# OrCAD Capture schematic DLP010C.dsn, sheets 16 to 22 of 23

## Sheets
16 PAGE 15 - DMD FLEX B: size Custom
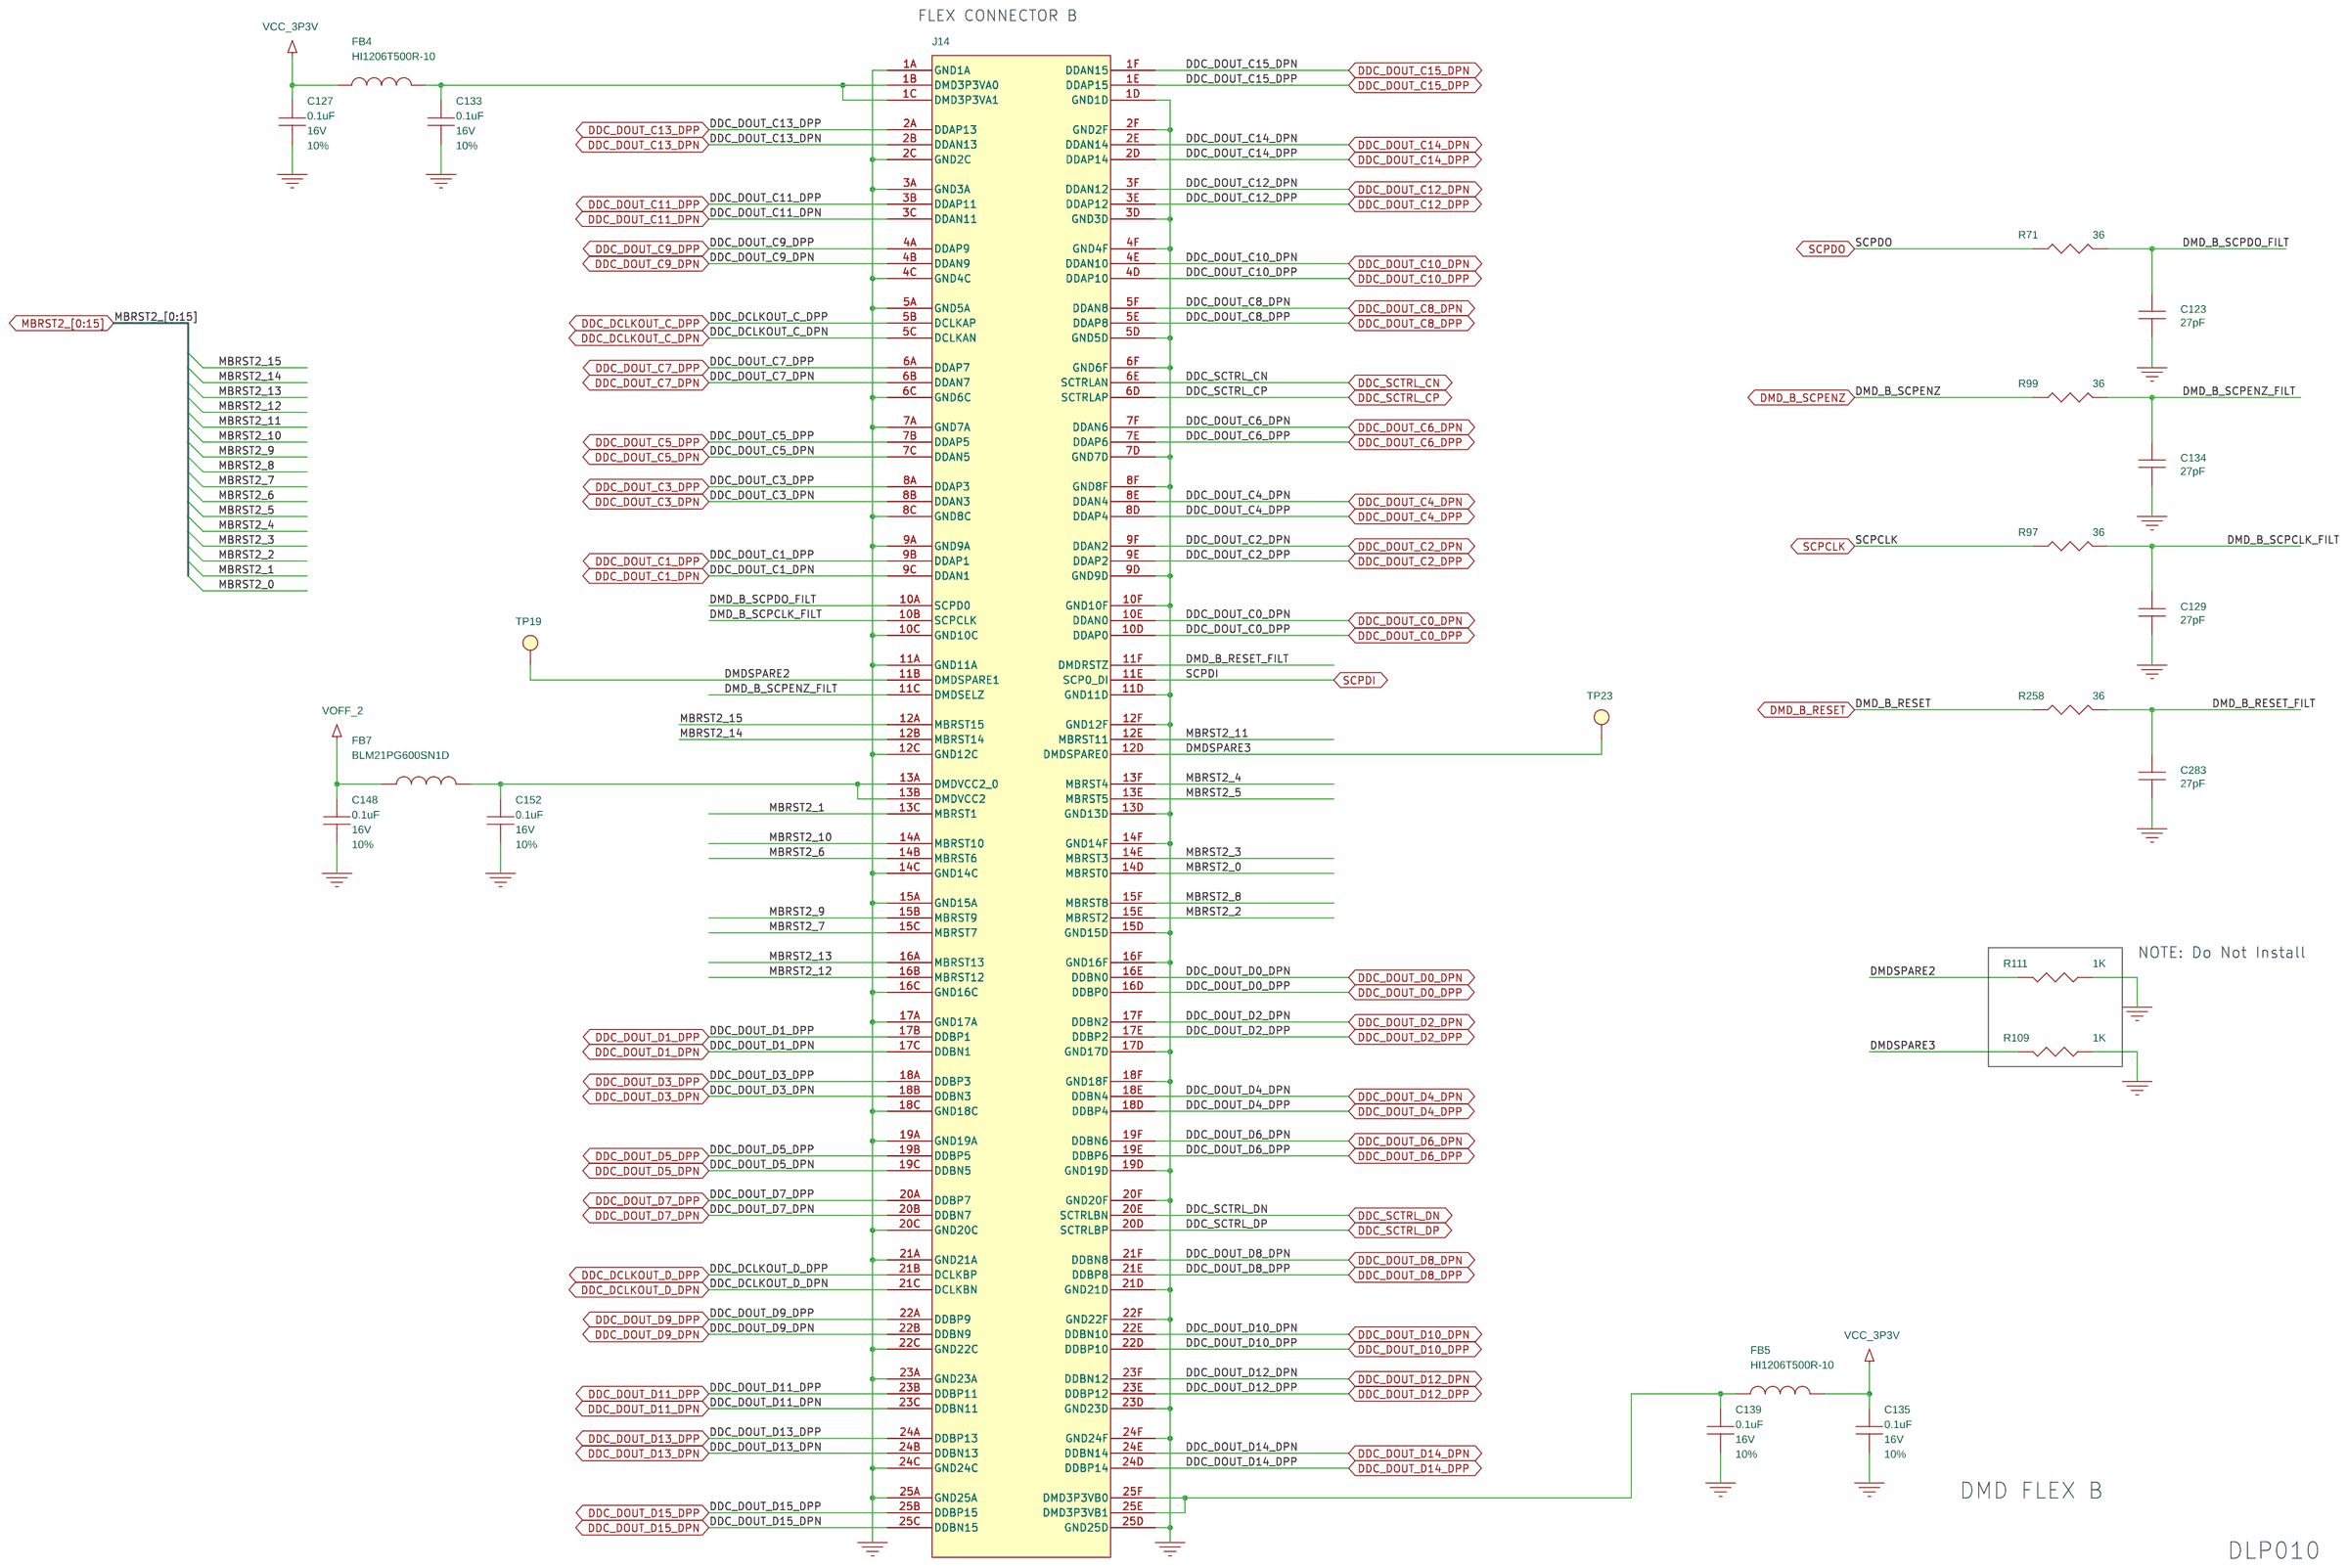
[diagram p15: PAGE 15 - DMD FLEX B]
17 PAGE 16 - EXP CONNECTOR 1: size Custom
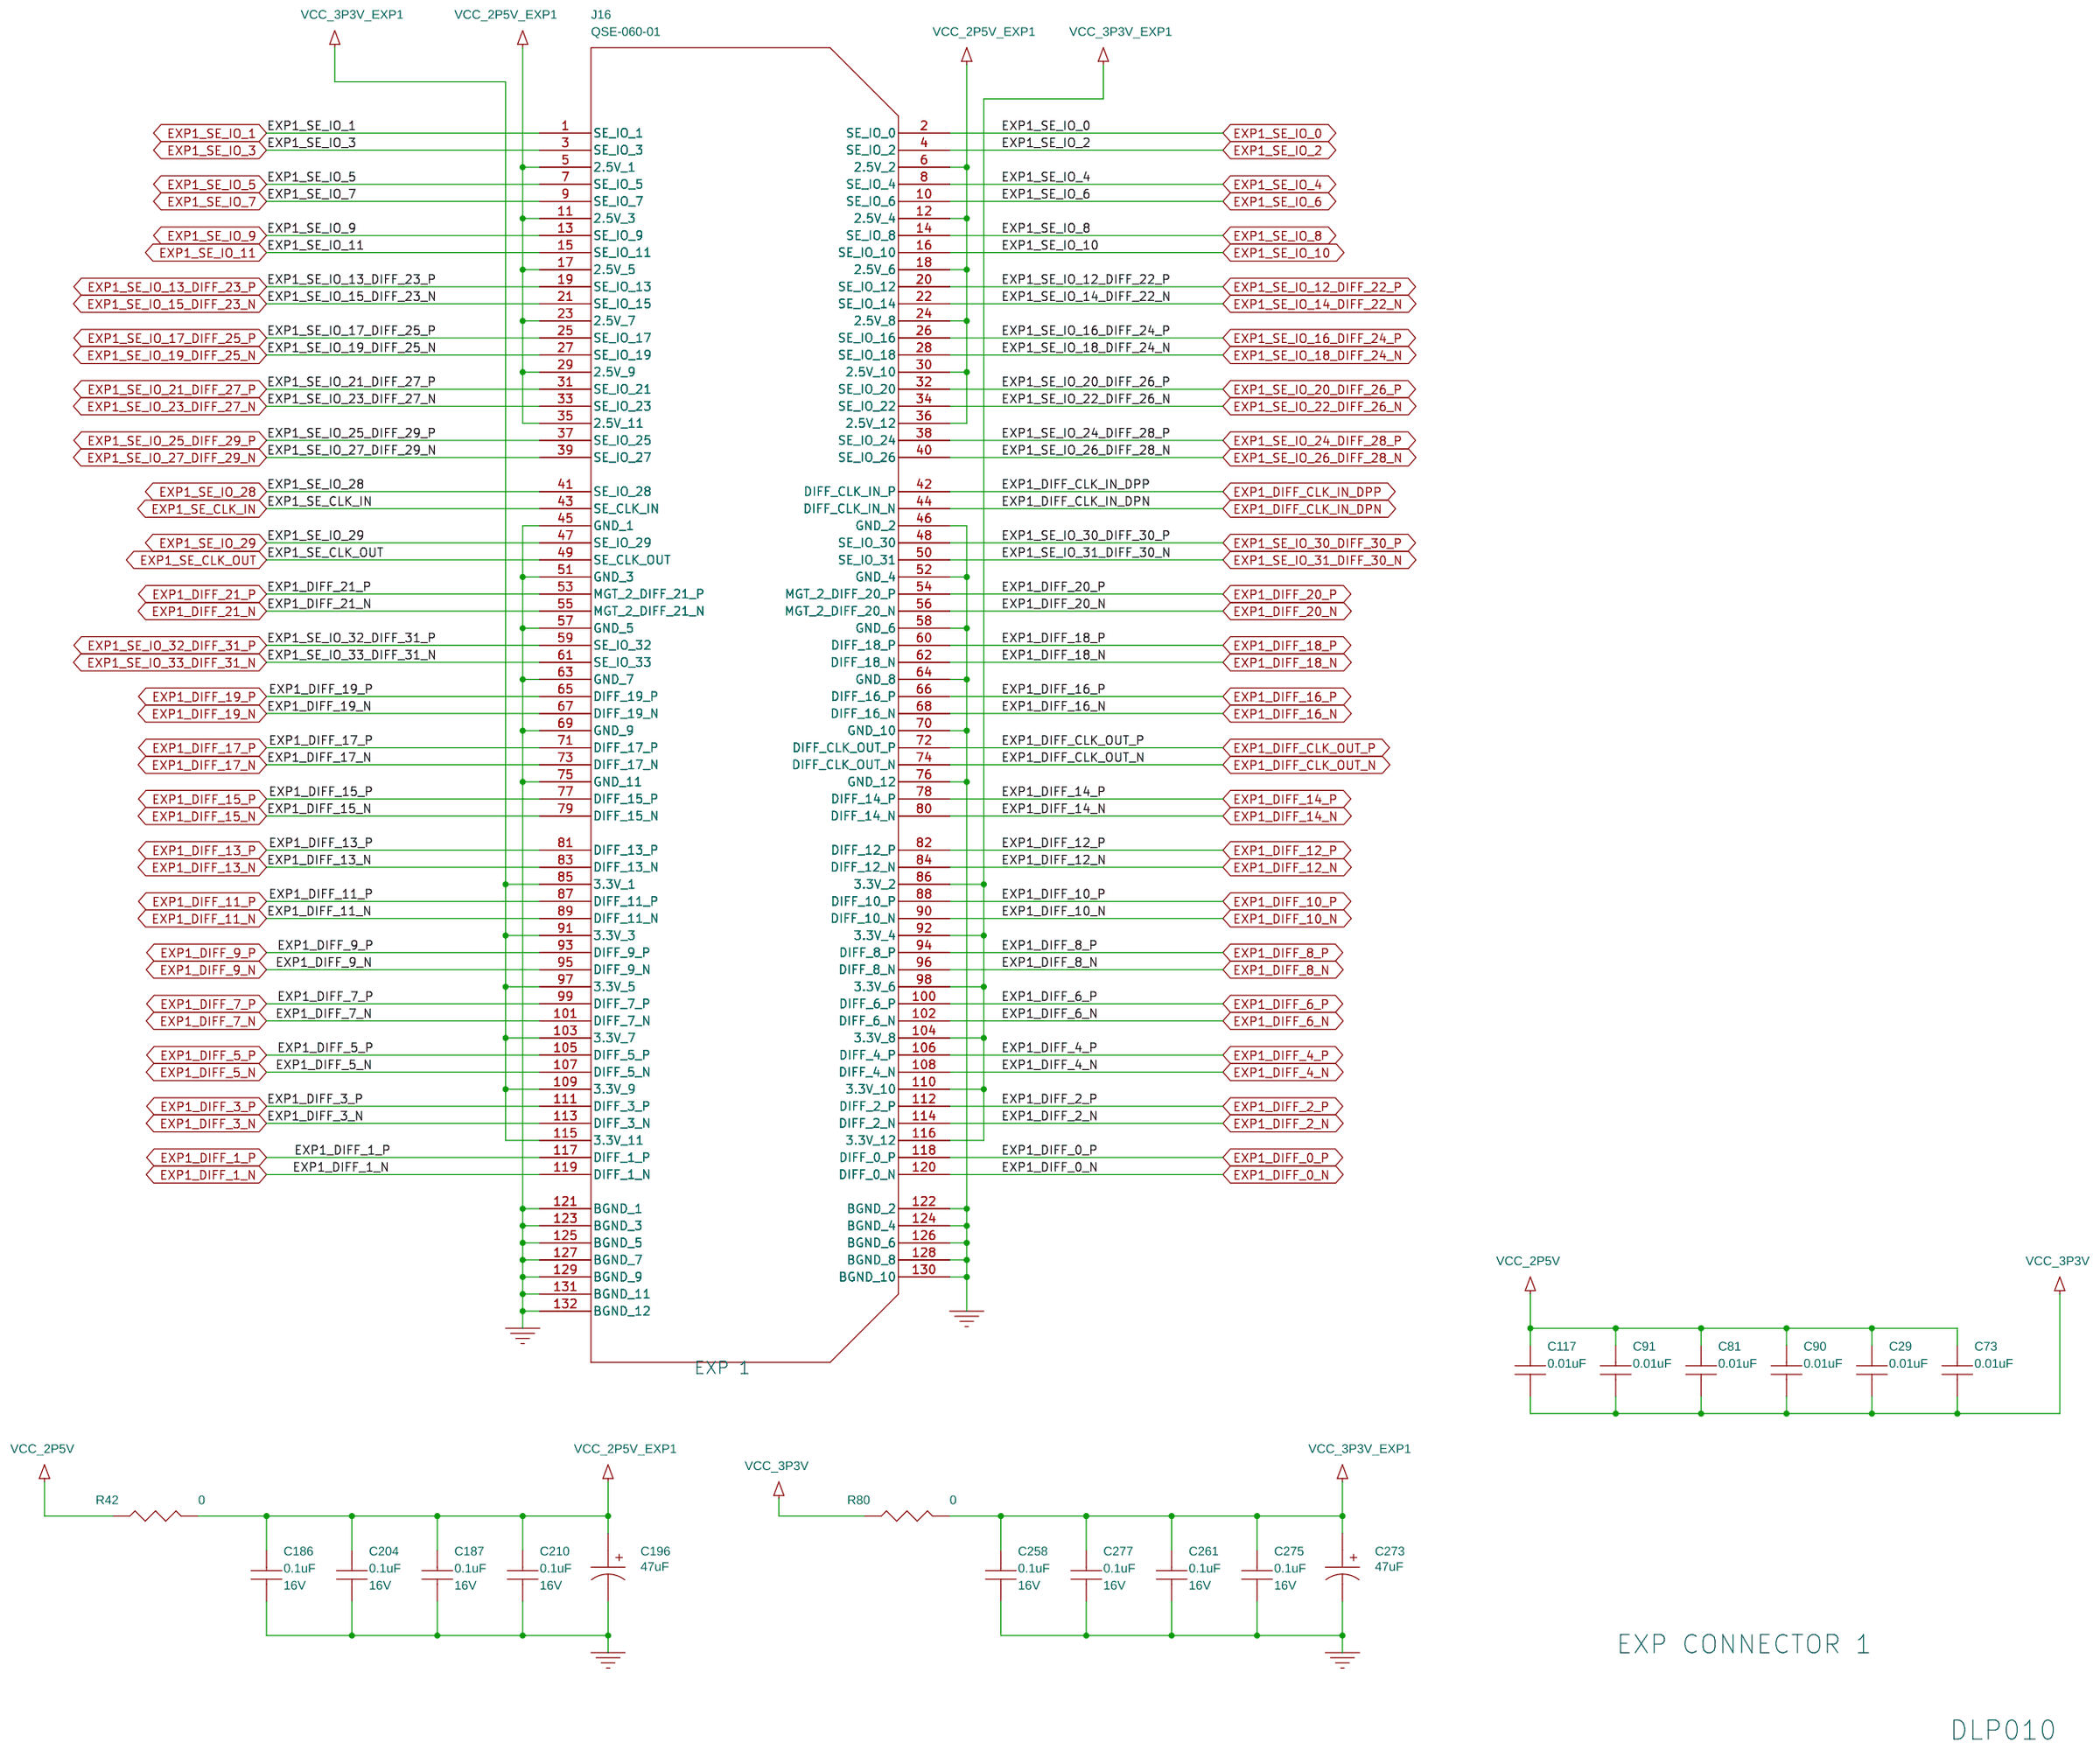
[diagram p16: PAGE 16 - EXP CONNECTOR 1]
18 PAGE 17 - EXP CONNECTOR 2: size Custom
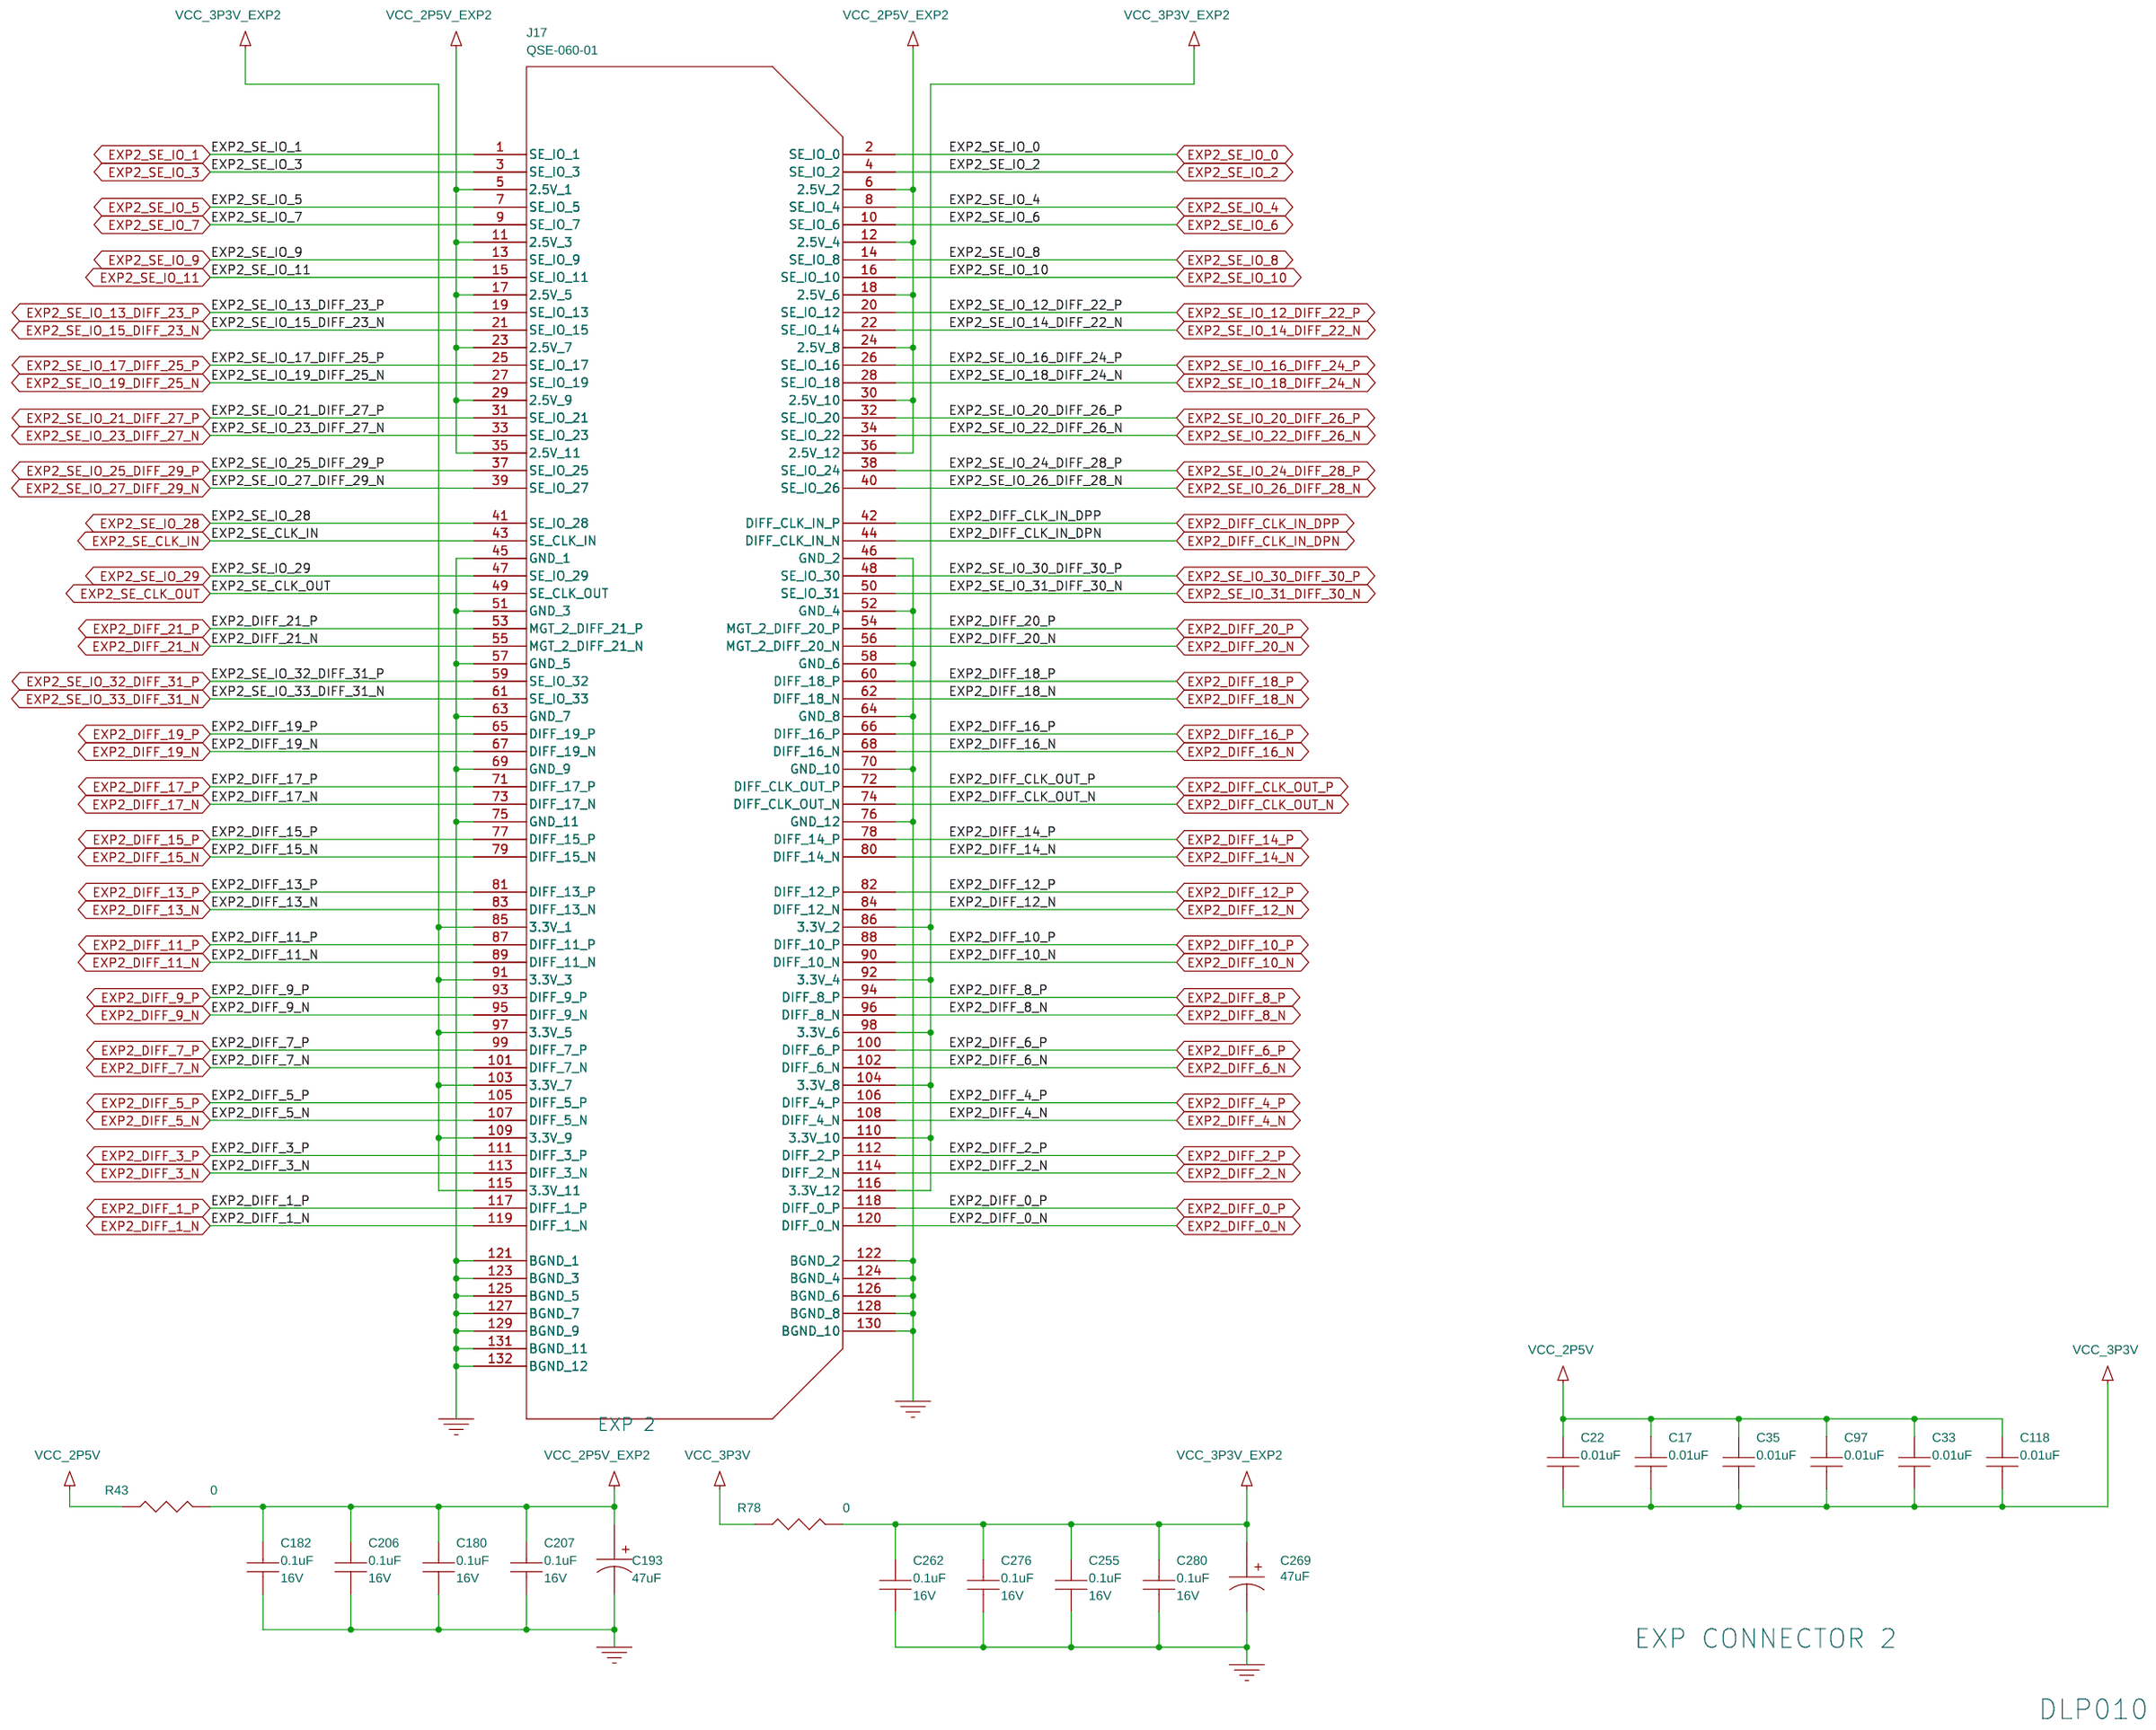
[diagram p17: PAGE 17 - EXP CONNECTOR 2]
19 PAGE 18 - POWER 1: size Custom
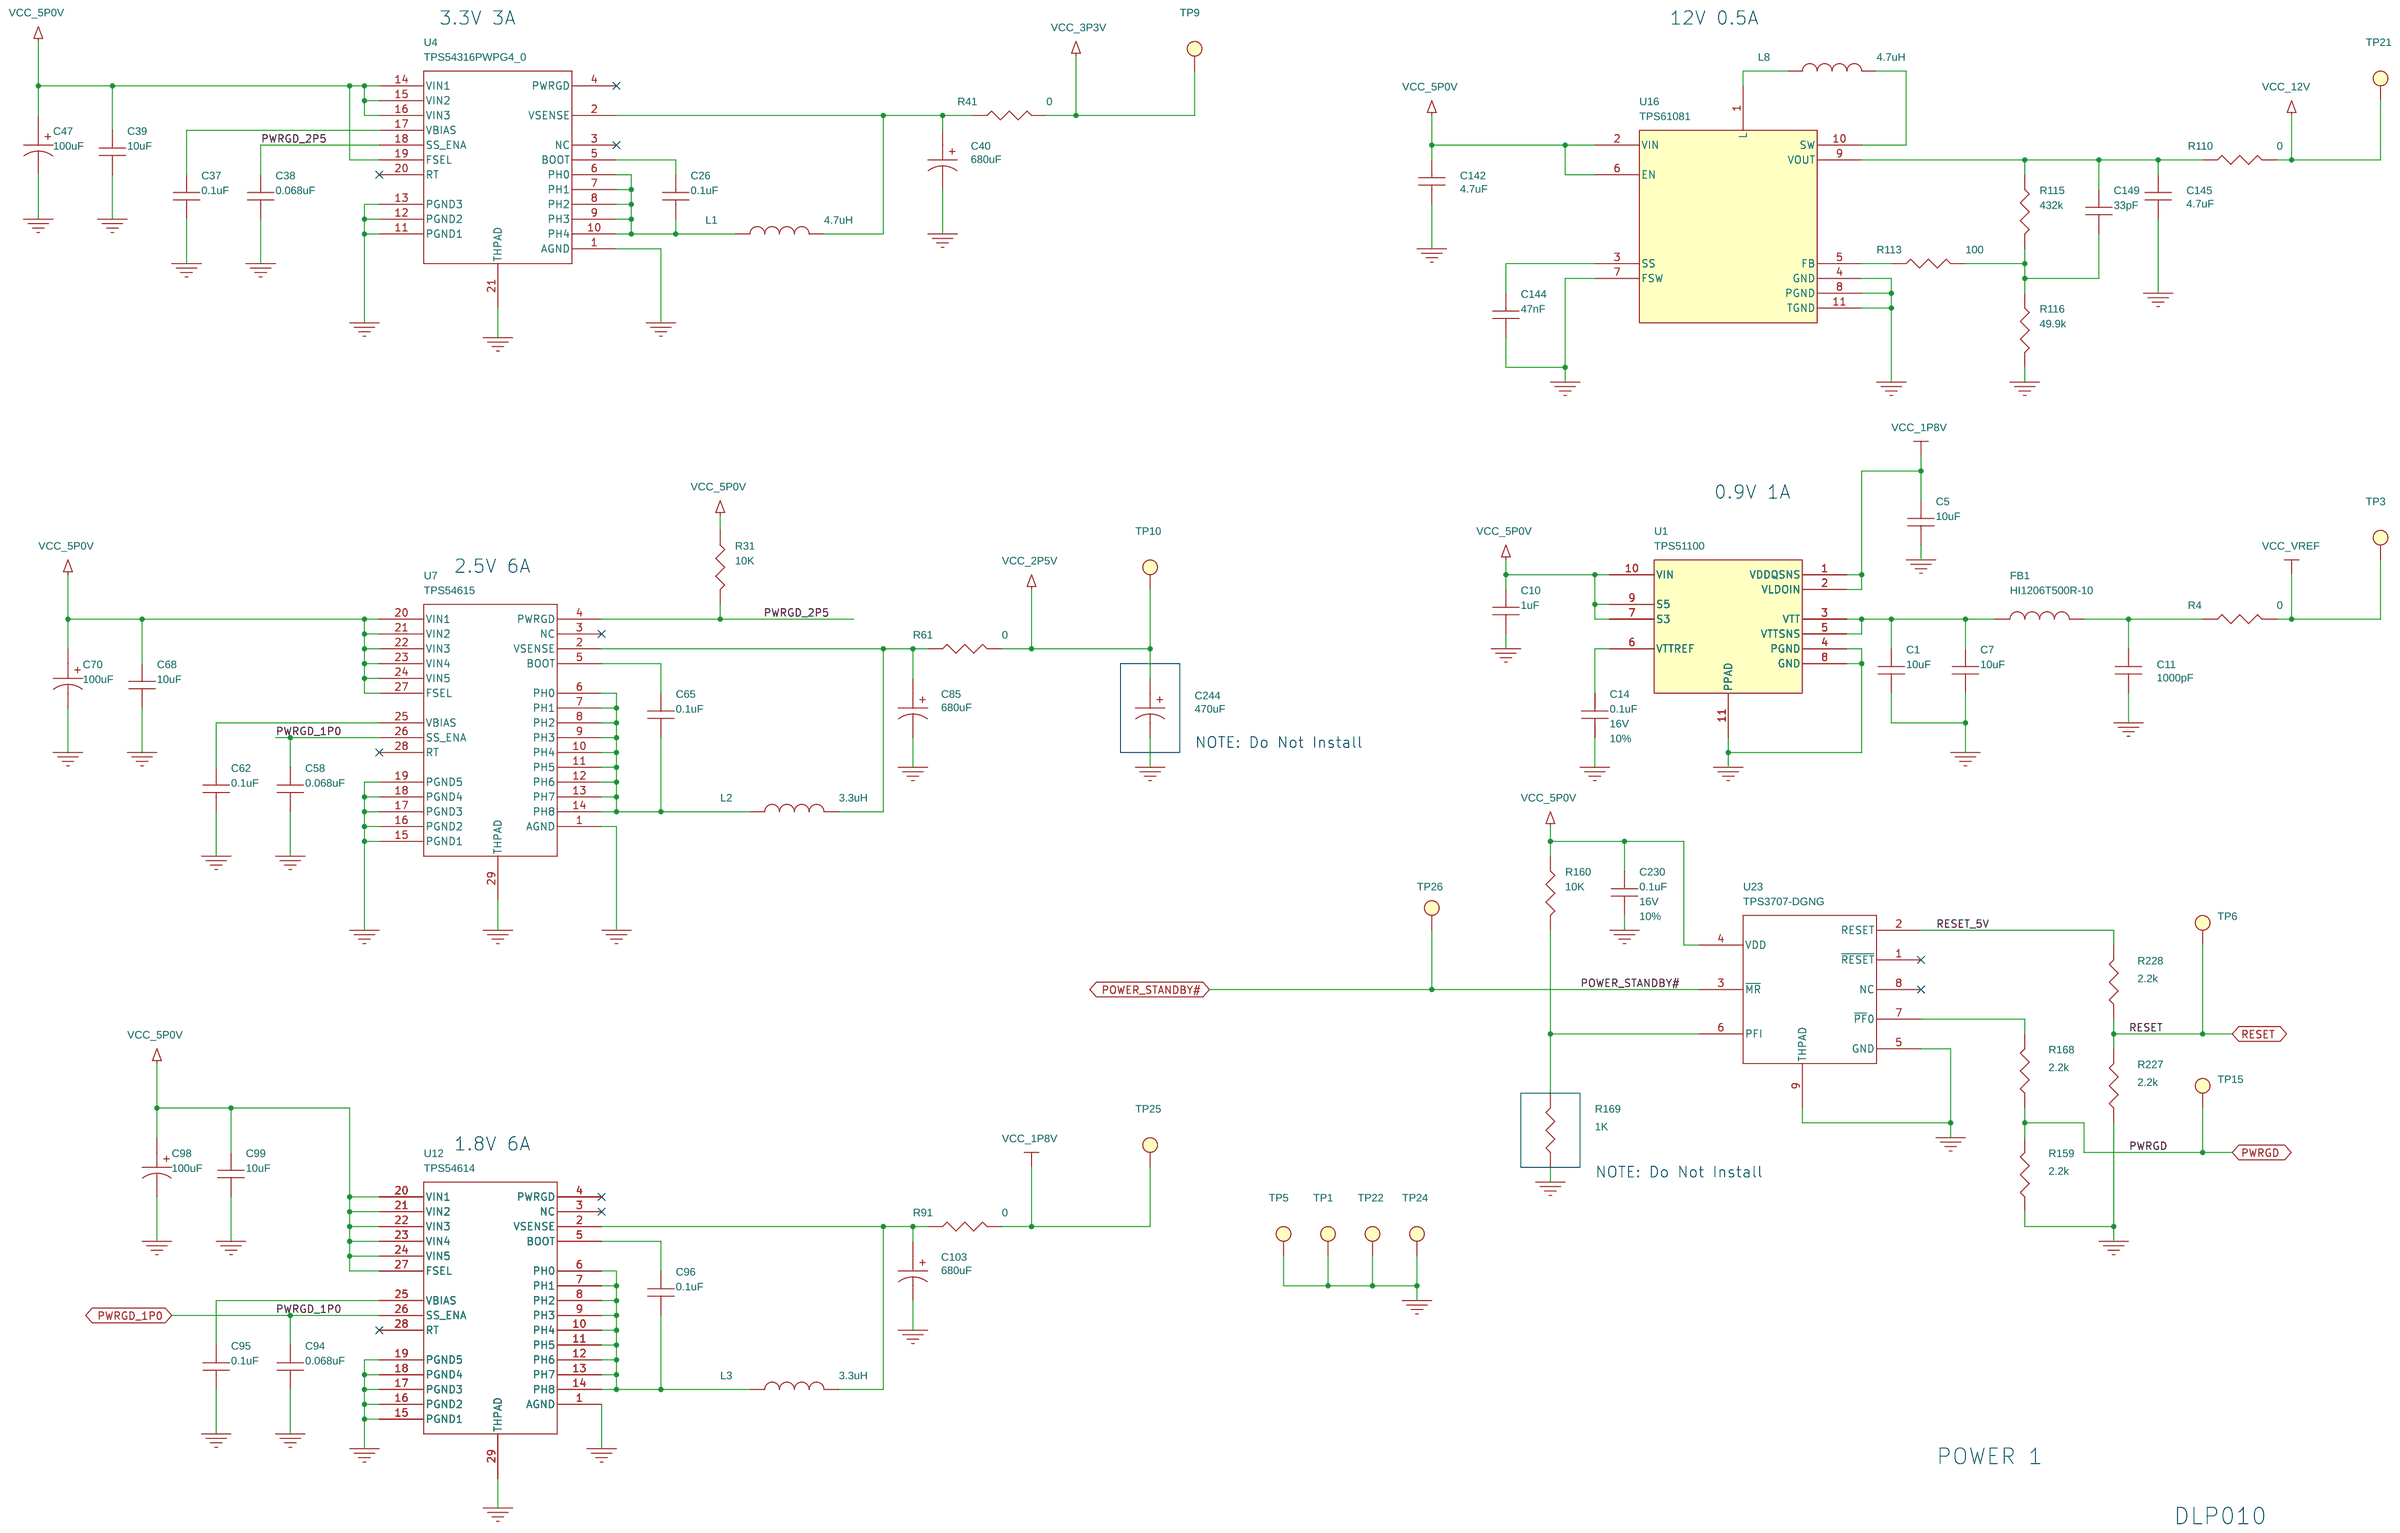
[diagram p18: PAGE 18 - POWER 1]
20 PAGE 19 - POWER 2: size Custom
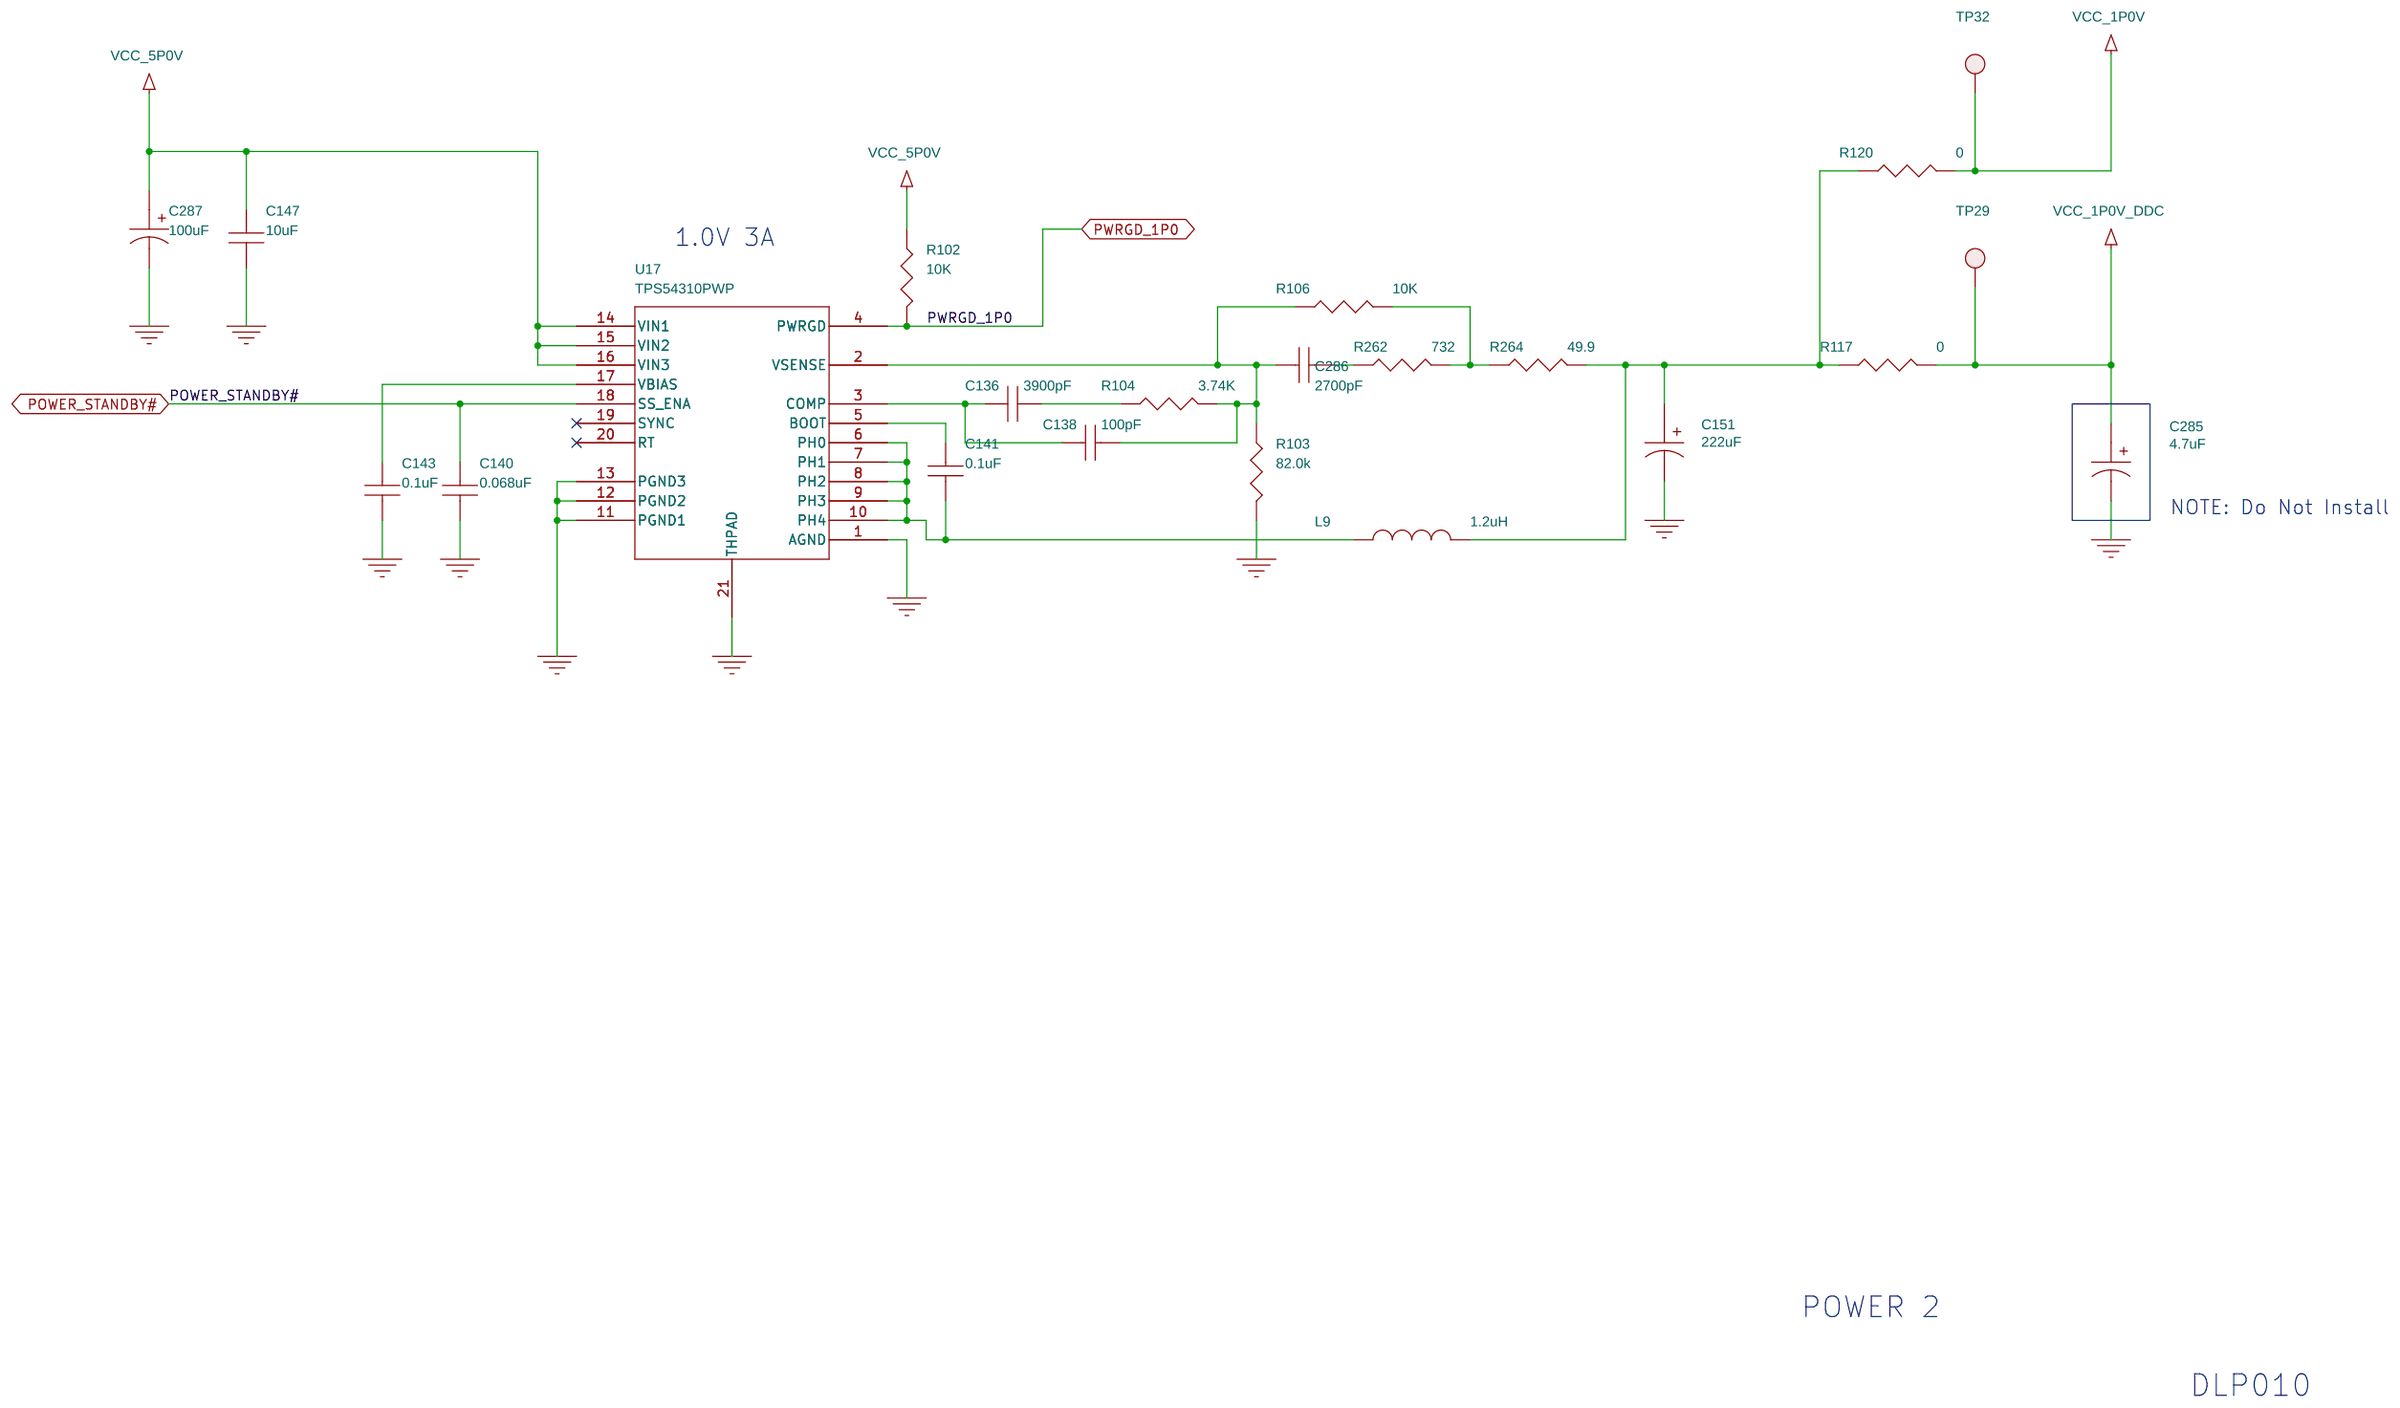
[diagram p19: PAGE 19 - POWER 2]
21 PAGE 20 - TEST HEADERS: size Custom
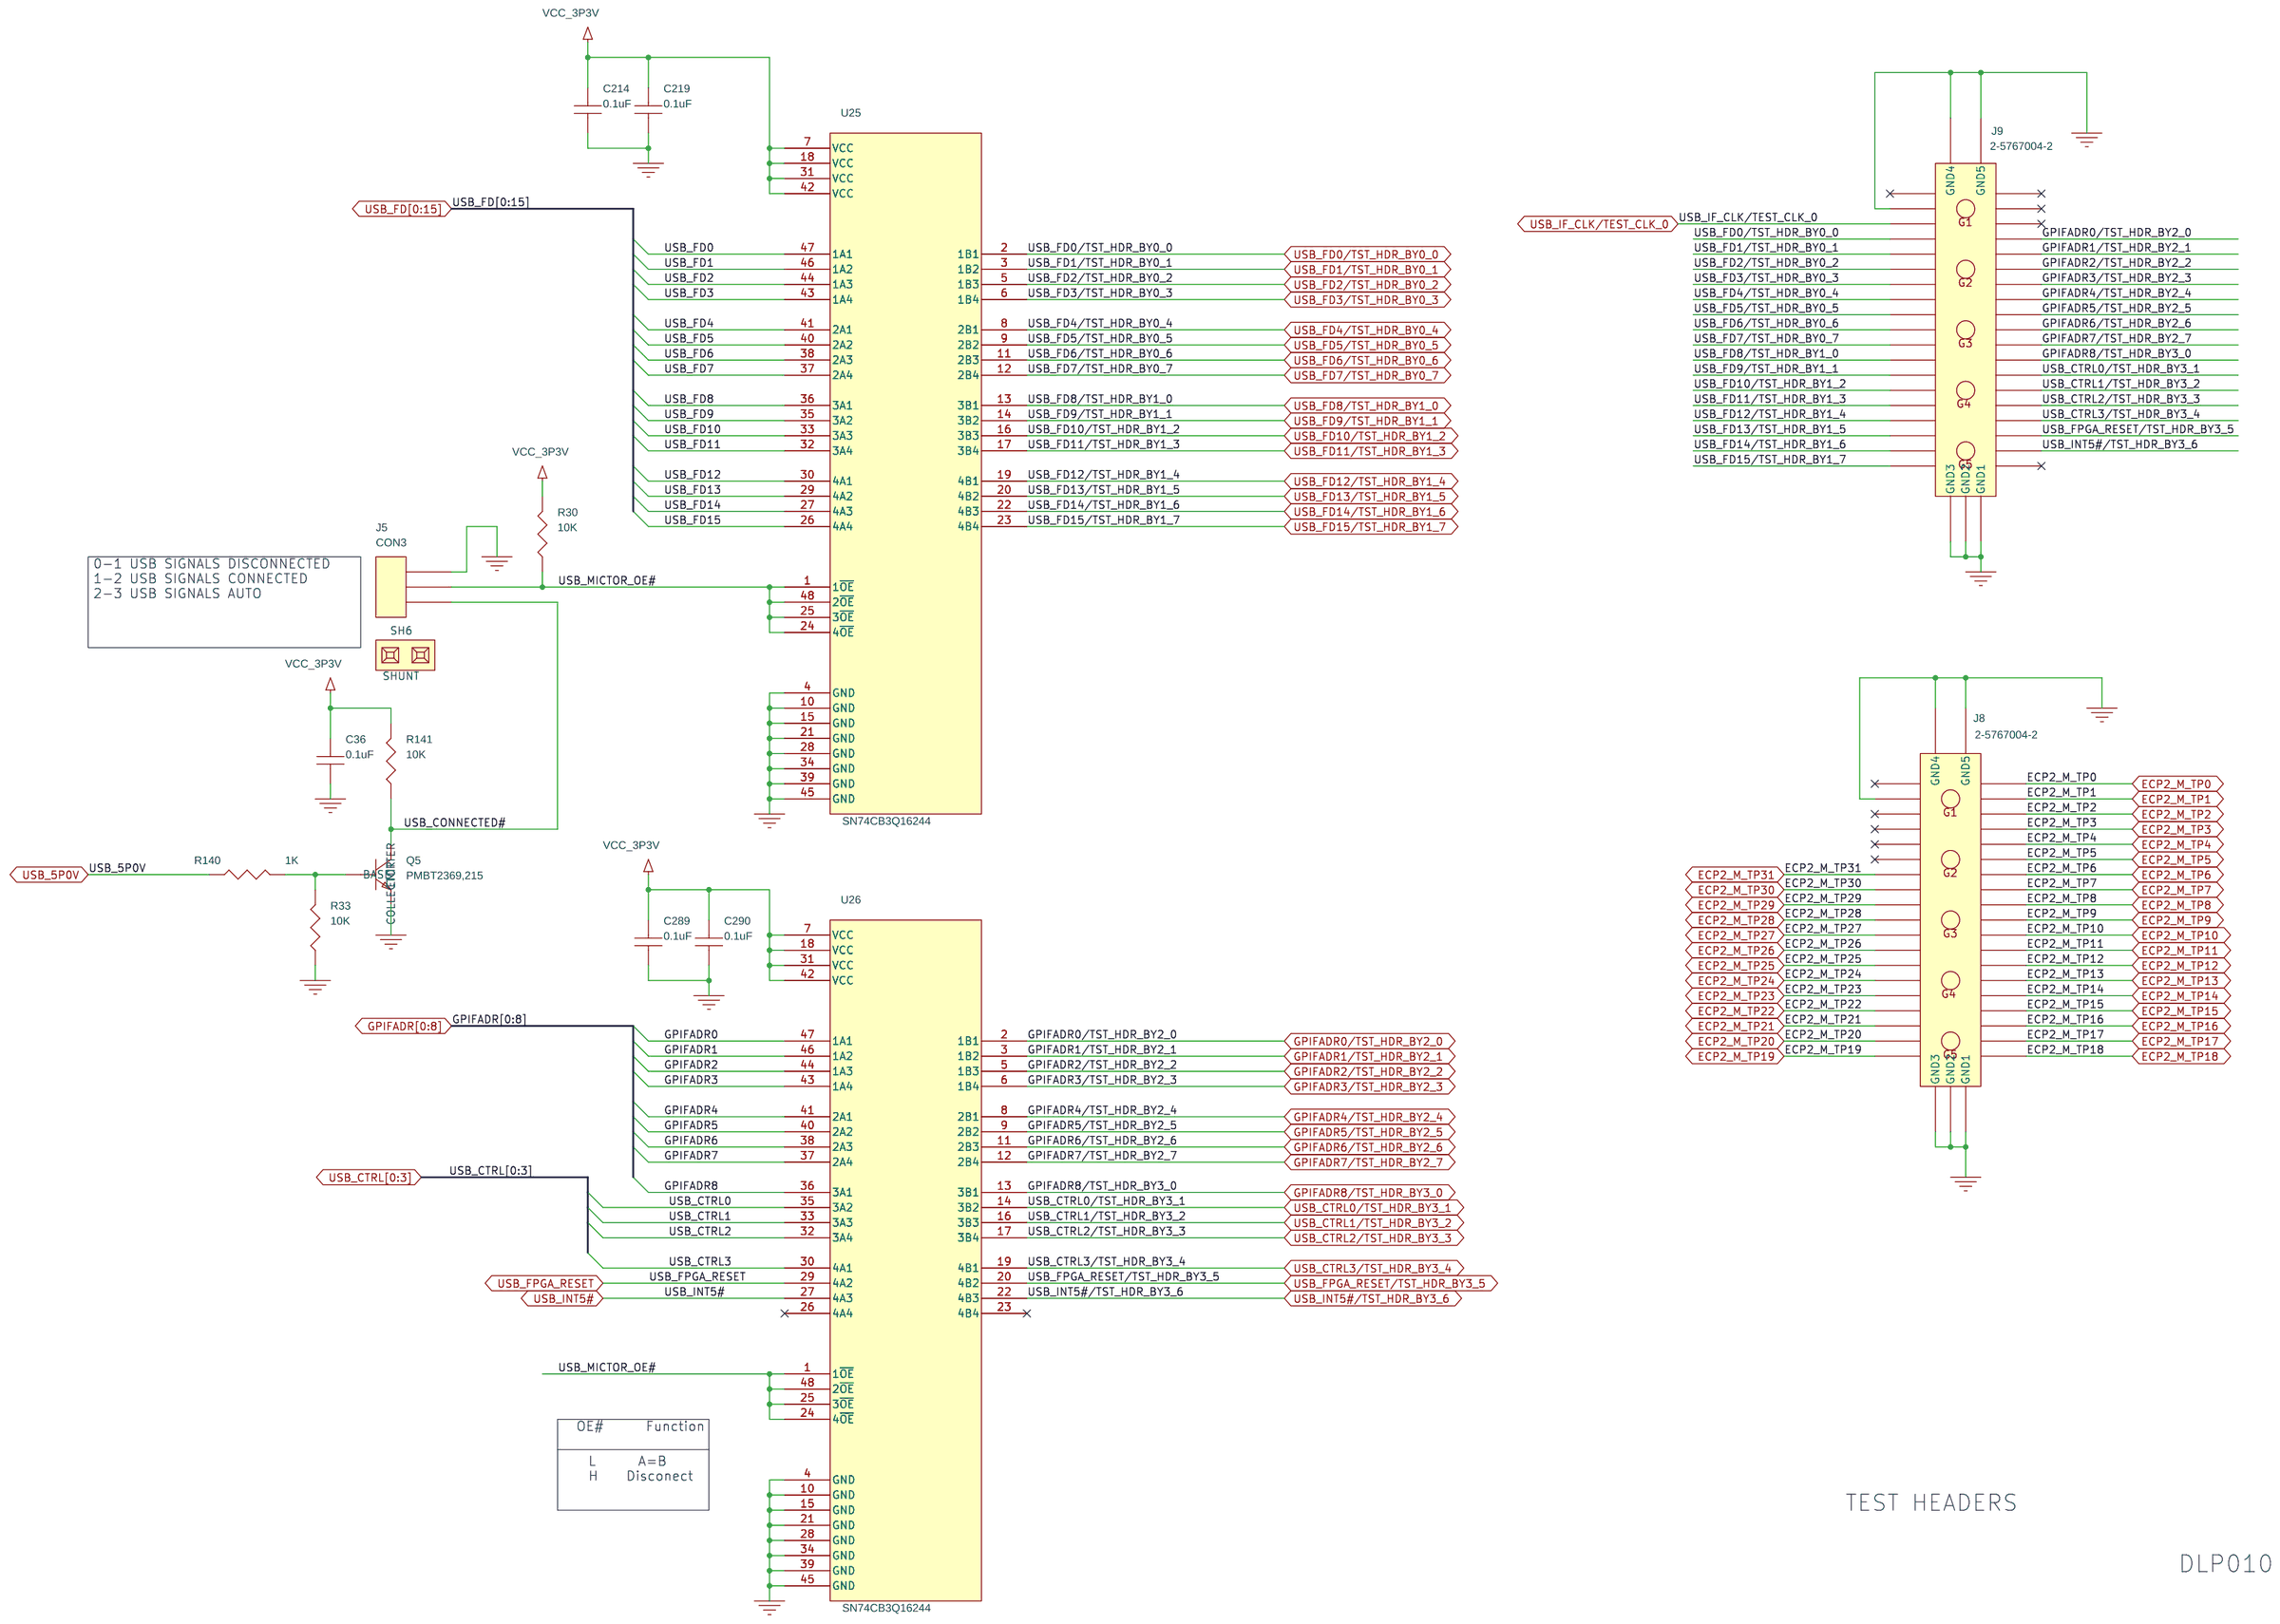
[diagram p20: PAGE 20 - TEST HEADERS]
22 PAGE 21 - USB CONTROLLER: size Custom
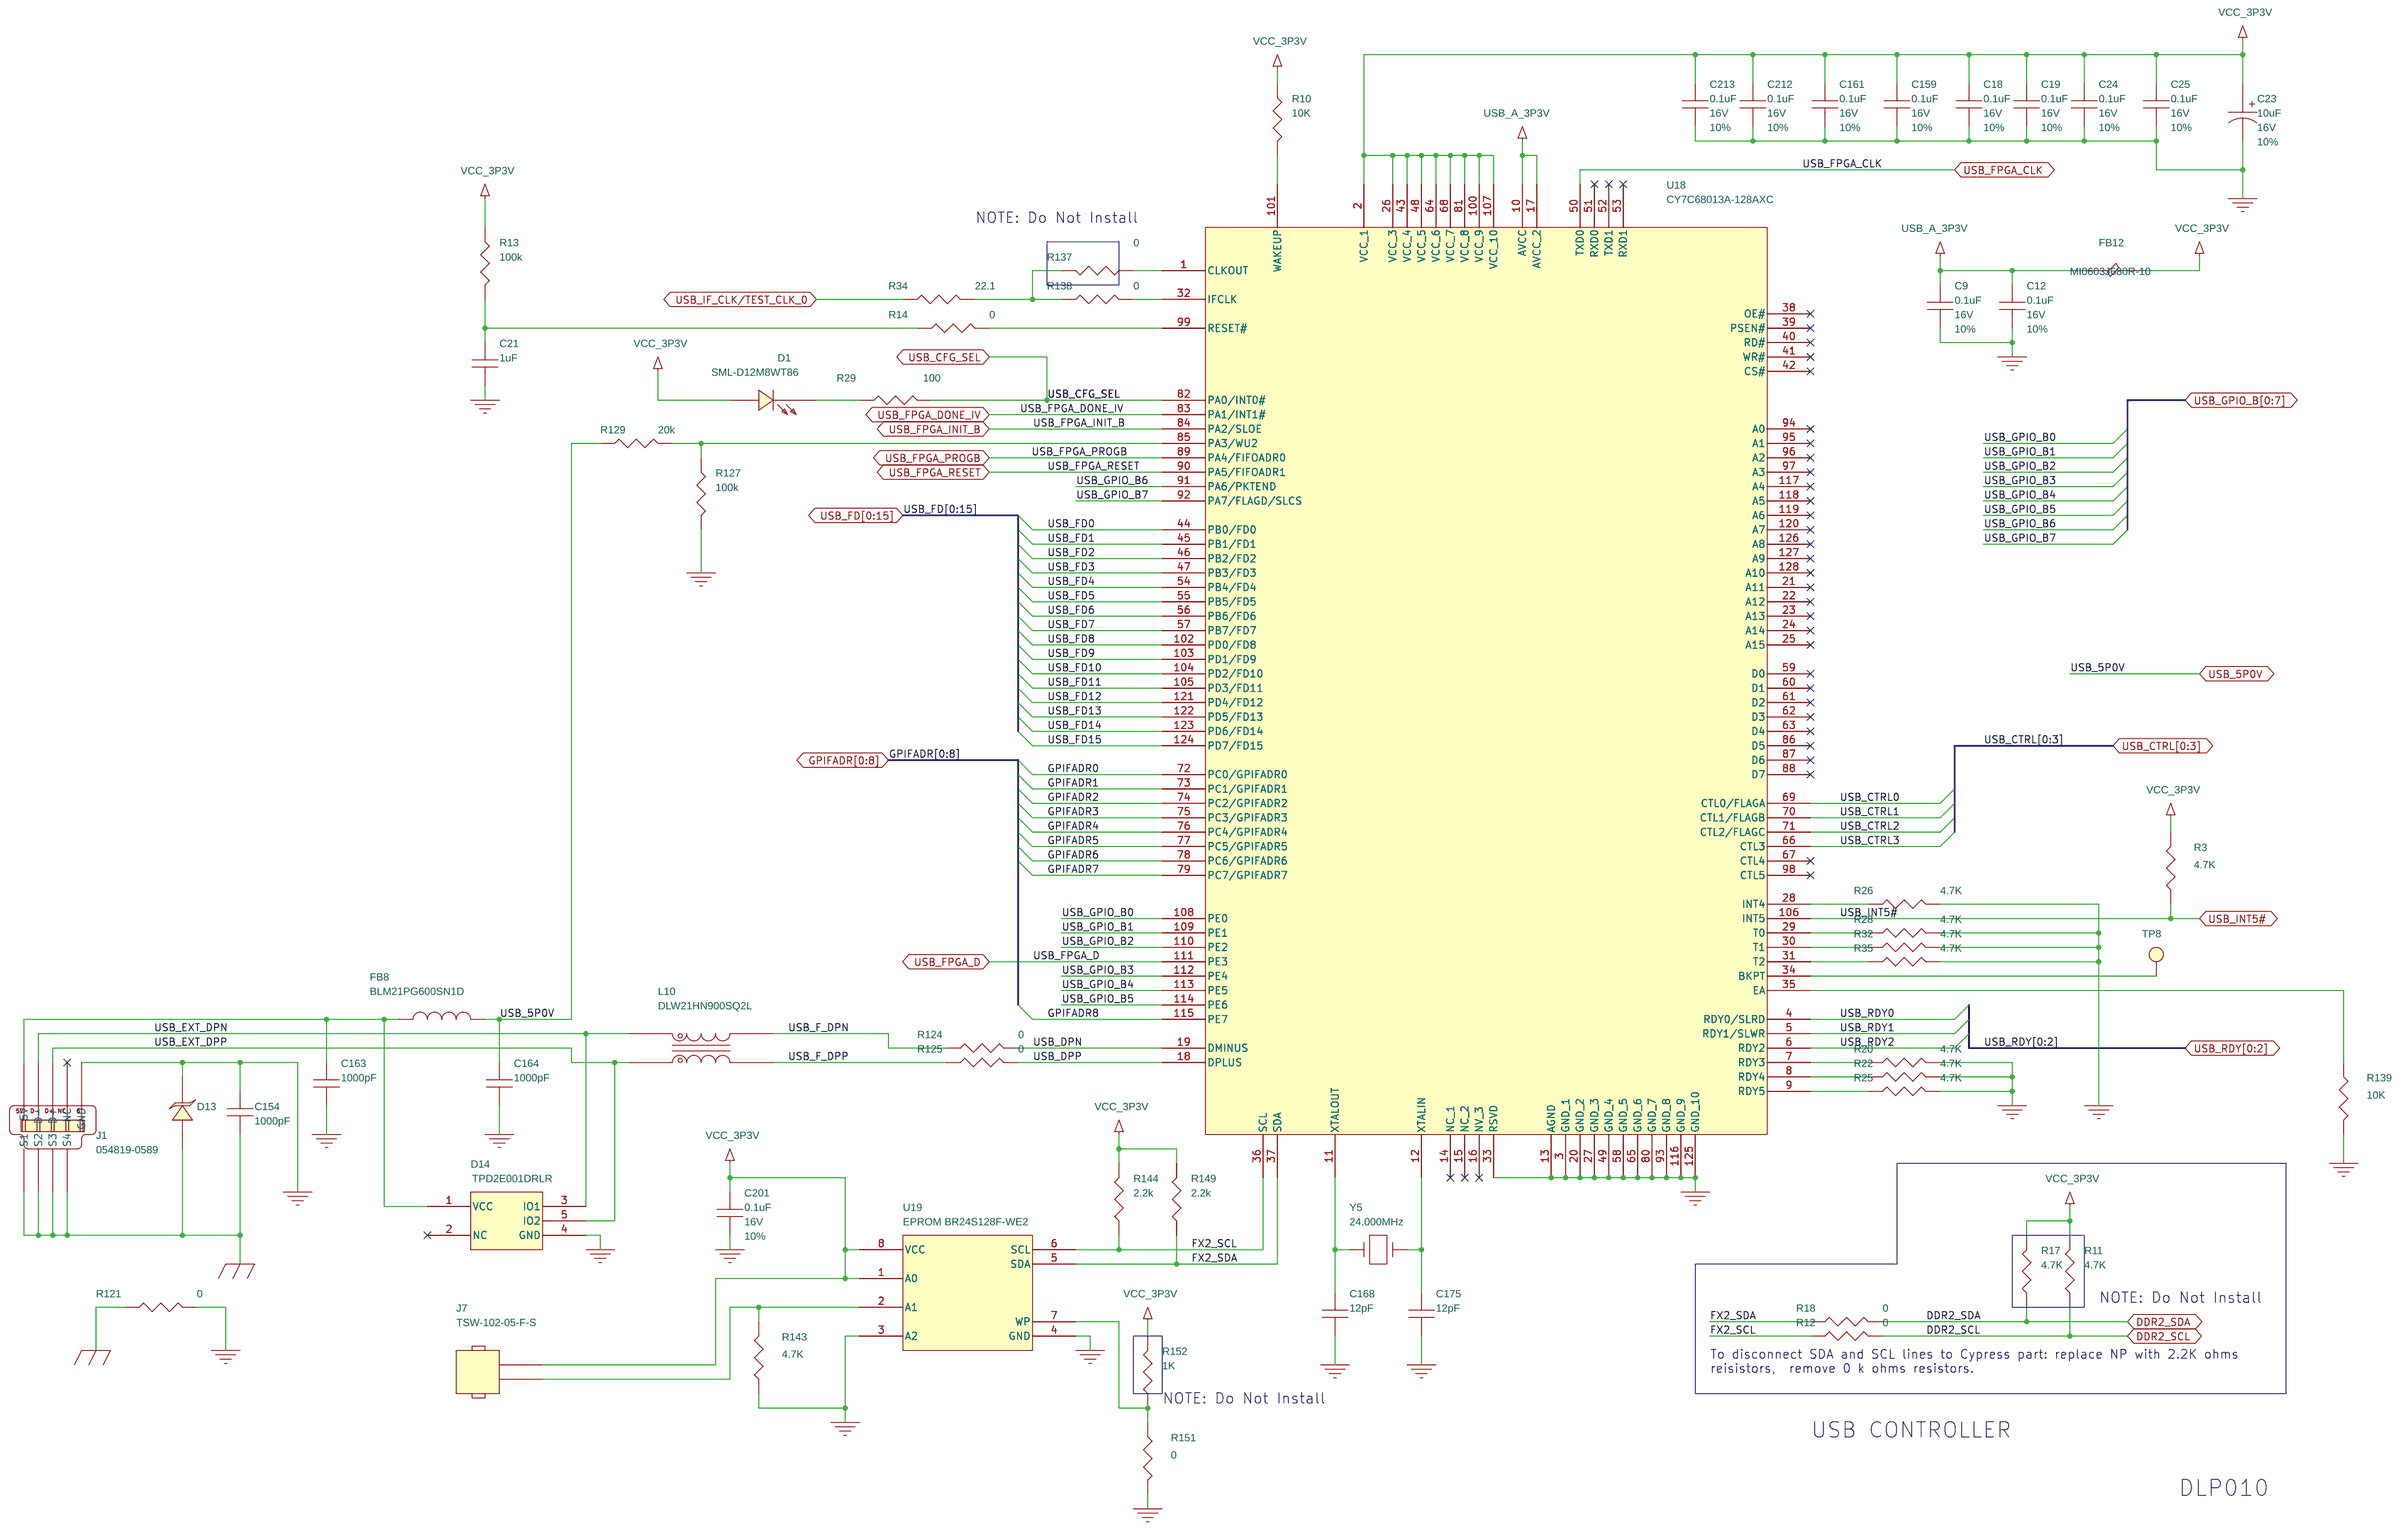
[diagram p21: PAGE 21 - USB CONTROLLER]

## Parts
sheet PAGE 15 - DMD FLEX B
C123  27pF  [0603]
C127  0.1uF  [0603]
C129  27pF  [0603]
C133  0.1uF  [0603]
C134  27pF  [0603]
C135  0.1uF  [0603]
C139  0.1uF  [0603]
C148  0.1uF  [0603]
C152  0.1uF  [0603]
C283  27pF  [0603]
FB4  HI1206T500R-10  [1206]
FB5  HI1206T500R-10  [1206]
FB7  BLM21PG600SN1D  [0805]
J14  7840-LVDS-DMD  [sm_conn_8397_board]
R71  36  [0603]
R97  36  [0603]
R99  36  [0603]
R109  1K  [0603]
R111  1K  [0603]
R258  36  [0603]
TP19  T POINT R  [25MILSQPOST]
TP23  T POINT R  [25MILSQPOST]
sheet PAGE 16 - EXP CONNECTOR 1
C29  0.01uF  [0603]
C73  0.01uF  [0603]
C81  0.01uF  [0603]
C90  0.01uF  [0603]
C91  0.01uF  [0603]
C117  0.01uF  [0603]
C186  0.1uF  [0603]
C187  0.1uF  [0603]
C196  47uF  [tant_b]
C204  0.1uF  [0603]
C210  0.1uF  [0603]
C258  0.1uF  [0603]
C261  0.1uF  [0603]
C273  47uF  [tant_b]
C275  0.1uF  [0603]
C277  0.1uF  [0603]
J16  QSE-060-01  [sm_qse_120]
R42  0  [1206]
R80  0  [1206]
sheet PAGE 17 - EXP CONNECTOR 2
C17  0.01uF  [0603]
C22  0.01uF  [0603]
C33  0.01uF  [0603]
C35  0.01uF  [0603]
C97  0.01uF  [0603]
C118  0.01uF  [0603]
C180  0.1uF  [0603]
C182  0.1uF  [0603]
C193  47uF  [tant_b]
C206  0.1uF  [0603]
C207  0.1uF  [0603]
C255  0.1uF  [0603]
C262  0.1uF  [0603]
C269  47uF  [tant_b]
C276  0.1uF  [0603]
C280  0.1uF  [0603]
J17  QSE-060-01  [sm_qse_120]
R43  0  [1206]
R78  0  [1206]
sheet PAGE 18 - POWER 1
C1  10uF  [1210]
C5  10uF  [1210]
C7  10uF  [1210]
C10  1uF  [0603]
C11  1000pF  [0402]
C14  0.1uF  [0603]
C26  0.1uF  [0603]
C37  0.1uF  [0603]
C38  0.068uF  [0603]
C39  10uF  [1210]
C40  680uF  [tant_d]
C47  100uF  [tant_d]
C58  0.068uF  [0603]
C62  0.1uF  [0603]
C65  0.1uF  [0603]
C68  10uF  [1210]
C70  100uF  [tant_d]
C85  680uF  [tant_d]
C94  0.068uF  [0603]
C95  0.1uF  [0603]
C96  0.1uF  [0603]
C98  100uF  [tant_d]
C99  10uF  [1210]
C103  680uF  [tant_d]
C142  4.7uF  [1206]
C144  47nF  [0603]
C145  4.7uF  [1206]
C149  33pF  [0603]
C230  0.1uF  [0603]
C244  470uF  [tant_d]
FB1  HI1206T500R-10  [1206]
L1  4.7uH  [sm_do3316p]
L2  3.3uH  [sm_do3316h]
L3  3.3uH  [sm_do3316h]
L8  4.7uH  [sm_sdr0403]
R4  0  [1206]
R31  10K  [0603]
R41  0  [1206]
R61  0  [1206]
R91  0  [1206]
R110  0  [1206]
R113  100  [0603]
R115  432k  [0603]
R116  49.9k  [0603]
R159  2.2k  [0603]
R160  10K  [0603]
R168  2.2k  [0603]
R169  1K  [0603]
R227  2.2k  [0603]
R228  2.2k  [0603]
TP1  T POINT R  [25MILSQPOST]
TP3  T POINT R  [25MILSQPOST]
TP5  T POINT R  [25MILSQPOST]
TP6  T POINT R  [25MILSQPOST]
TP9  T POINT R  [25MILSQPOST]
TP10  T POINT R  [25MILSQPOST]
TP15  T POINT R  [25MILSQPOST]
TP21  T POINT R  [25MILSQPOST]
TP22  T POINT R  [25MILSQPOST]
TP24  T POINT R  [25MILSQPOST]
TP25  T POINT R  [25MILSQPOST]
TP26  T POINT R  [25MILSQPOST]
U1  TPS51100  [10DGQ]
U4  TPS54316PWPG4_0  [20pwp]
U7  TPS54615  [28PWP]
U12  TPS54614  [28PWP]
U16  TPS61081  [sm_ti_drc10]
U23  TPS3707-DGNG  [8MSOP]
sheet PAGE 19 - POWER 2
C136  3900pF  [0603]
C138  100pF  [0603]
C140  0.068uF  [0603]
C141  0.1uF  [0603]
C143  0.1uF  [0603]
C147  10uF  [1210]
C151  222uF  [tant_c]
C285  4.7uF  [tant_c]
C286  2700pF  [0603]
C287  100uF  [tant_d]
L9  1.2uH  [sm_do1813h]
R102  10K  [0603]
R103  82.0k  [0603]
R104  3.74K  [0603]
R106  10K  [0603]
R117  0  [1206]
R120  0  [1206]
R262  732  [0603]
R264  49.9  [0603]
TP29  T POINT R  [25MILSQPOST]
TP32  T POINT R  [25MILSQPOST]
U17  TPS54310PWP  [20PWP]
sheet PAGE 20 - TEST HEADERS
C36  0.1uF  [0603]
C214  0.1uF  [0603]
C219  0.1uF  [0603]
C289  0.1uF  [0603]
C290  0.1uF  [0603]
J5  CON3  [th_conn_3pos_100]
J8  2-5767004-2  [CONN38]
J9  2-5767004-2  [CONN38]
Q5  PMBT2369,215  [sot23]
R30  10K  [0603]
R33  10K  [0603]
R140  1K  [0603]
R141  10K  [0603]
SH6  SHUNT
U25  SN74CB3Q16244  [SOP40P640X120-48N]
U26  SN74CB3Q16244  [SOP40P640X120-48N]
sheet PAGE 21 - USB CONTROLLER
C9  0.1uF  [0603]
C12  0.1uF  [0603]
C18  0.1uF  [0603]
C19  0.1uF  [0603]
C21  1uF  [0603]
C23  10uF  [tant_a]
C24  0.1uF  [0603]
C25  0.1uF  [0603]
C154  1000pF  [0402]
C159  0.1uF  [0603]
C161  0.1uF  [0603]
C163  1000pF  [0402]
C164  1000pF  [0402]
C168  12pF  [0603]
C175  12pF  [0603]
C201  0.1uF  [0603]
C212  0.1uF  [0603]
C213  0.1uF  [0603]
D1  SML-D12M8WT86  [sm_led_0603]
D13  DIODE TS  [sm_dio_sma]
D14  TPD2E001DRLR  [sm_sot553-5_2]
FB8  BLM21PG600SN1D  [0805]
FB12  MI0603J680R-10  [0603]
J1  054819-0589  [MOLEX_054819-0589]
J7  TSW-102-05-F-S  [jumper2]
L10  DLW21HN900SQ2L  [sm_cm14_0805]
R3  4.7K  [0603]
R10  10K  [0603]
R11  4.7K  [0603]
R12  0  [0603]
R13  100k  [0603]
R14  0  [0603]
R17  4.7K  [0603]
R18  0  [0603]
R20  4.7K  [0603]
R22  4.7K  [0603]
R25  4.7K  [0603]
R26  4.7K  [0603]
R28  4.7K  [0603]
R29  100  [0402]
R32  4.7K  [0603]
R34  22.1  [0603]
R35  4.7K  [0603]
R121  0  [0603]
R124  0  [0603]
R125  0  [0603]
R127  100k  [0603]
R129  20k  [0603]
R137  0  [0603]
R138  0  [0603]
R139  10K  [0603]
R143  4.7K  [0603]
R144  2.2k  [0603]
R149  2.2k  [0603]
R151  0  [0603]
R152  1K  [0603]
TP8  T POINT R  [25MILSQPOST]
U18  CY7C68013A-128AXC  [sm_tpqf128_cypress]
U19  EPROM BR24S128F-WE2  [SOIC127P620X170-8N]
Y5  24.000MHz  [sm_xtal_275x200]

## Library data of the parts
C123 C129 C134 C283 = CAP_NP: Manuf: KEMET; PartNumber: C0603C270J5GAC7867; Tolerance: C0G; Voltage: 50
C36 C127 C133 C135 C139 C148 C152 C180 C182 C186 C187 C204 C206 C207 C210 C214 C219 C255 C258 C261 C262 C275-C277 C280 C289 C290 = CAP_NP: Manuf: Kemet; PartNumber: C0603C104K4RACTU; Tolerance: 10%; Voltage: 16V
FB4 FB5 = INDUCTOR: Current: 6A; Impedance: 50ohms @ 100Mhz; Manuf: Steward
FB7 = INDUCTOR: Current: 3A; Impedance: 60; Manuf: Murata
J14 = 7840-LVDS-DMD: DNI: DNI; Manuf: Amphenol; Notes: DNI - Install during test; PartNumber: 7840-002
R71 R97 R99 R258 = R_v2: Manuf: Panasonic; PartNumber: ERJ-3GEYJ360V; Tolerance: %5
R109 R111 = R_v2: DNI: DNI; Manuf: Panasonic; Notes: DNI; PartNumber: ERJ-3GEYJ102V
TP19 TP23 = T_POINT_R: DNI: DNI; Manuf: Not-a-part; PartNumber: Not-a-part
C17 C22 C29 C33 C35 C73 C81 C90 C91 C97 C117 C118 = CAP_NP: Manuf: Kemet; PartNumber: C0603C103K5RACTU; ROOM: SODIMM; Tolerance: 10%; Voltage: 50V
C193 C196 C269 C273 = CAP_POL: Manuf: AVX; PartNumber: TAJB476M006RNJ; Tolerance: 20%; Voltage: 6.3V
J16 J17 = QSE-060-01: Manuf: Samtec; PartNumber: QSE-060-01-F-D-A
R4 R41-R43 R61 R78 R80 R91 R110 = R_v2: Manuf: Stackpole; PartNumber: RMCF1206ZG0R00; ROOM: Power
C1 C5 C7 C39 C68 C99 C147 = CAP_NP: Manuf: Kemet; PartNumber: C1210C106K8PACTU; ROOM: Power; TempCoeff: X5R; Tolerance: 10%; Voltage: 10V
C10 = CAP_NP: Manuf: TDK; PartNumber: C1608X7R1C105K; ROOM: Power; Tolerance: 10%; Voltage: 16V
C11 = CAP_NP: Manuf: TDK; PartNumber: C1005X7R1H102K; ROOM: Power; Tolerance: X7R; Voltage: 50V
C14 C26 C37 C62 C65 C95 C96 C141 C143 C230 = CAP_NP: Manuf: Kemet; PartNumber: C0603C104K4RACTU; ROOM: Power; Tolerance: 10%; Voltage: 16V
C38 C58 C94 C140 = CAP_NP: Manuf: Kemet; PartNumber: C0603C683J5RACTU; ROOM: Power; Tolerance: 5%; Voltage: 50V
C40 C85 C103 = CAP_POL: ESR: 0.023; Manuf: AVX; PartNumber: TPME687M006R0023; ROOM: Power; Tolerance: 20%; Voltage: 6.3V
C47 C70 C98 C287 = CAP_POL: Manuf: AVX; PartNumber: TPSD107K010R0065; ROOM: Power; Tolerance: 10%; Voltage: 10V
C142 C145 = CAP_NP: Manuf: TDK; PartNumber: C3216X7R1E475K; ROOM: Power; Tolerance: 10%; Voltage: 25V; tempCoef: X7R
C144 = CAP_NP: Manuf: Yageo; PartNumber: CC0603KRX7R8BB473; ROOM: Power; TempCoeff: X7R; Tolerance: 10%; Voltage: 25V
C149 = CAP_NP: Manuf: KEMET; PartNumber: C0603C330J5GAC7411; ROOM: Power; TempCoeff: C0G; Tolerance: 5%; Voltage: 50V
C244 = CAP_POL: DNI: DNI; ESR: 0.023; Manuf: AVX; Notes: DNI; PartNumber: TAJD477K006RNJ; ROOM: Power
FB1 = INDUCTOR: Current: 6A; Impedance: 50ohms @ 100Mhz; Manuf: Steward; ROOM: Power
L1 = INDUCTOR: Irms: 4.8 A; Manuf: CoilCraft; PartNumber: DO3316P-472MLD; RDC: 0.018; ROOM: Power; Tolerance: 20
L2 L3 = INDUCTOR: Irms: 4.8 A; Manuf: CoilCraft; PartNumber: DO3316H-332MLD; RDC: 0.014; ROOM: Power; Tolerance: 20
L8 = INDUCTOR: Irms: 1.7 A; Manuf: Bourns; PartNumber: SDR0403-4R7ML; RDC: 0.094 Ohms; ROOM: Power; Tolerance: 20
R31 R102 R160 = R_v2: Manuf: Panasonic; PartNumber: ERJ-3GEYJ103V; ROOM: Power; Tolerance: %1
R113 = R_v2: Manuf: Bourns; PartNumber: CR0603-JW-101ELF; ROOM: Power; Tolerance: 5%
R115 = R_v2: Manuf: Bourns; PartNumber: CR0603-FX-4323ELF; ROOM: Power; Tolerance: 1%
R116 = R_v2: Manuf: Bourns; PartNumber: CR0603-FX-4992ELF; ROOM: Power; Tolerance: 1%
R159 R168 R227 R228 = R_v2: Manuf: Panasonic; PartNumber: ERJ-3GEYJ222V; ROOM: Power
R169 = R_v2: DNI: DNI; Manuf: Panasonic; Notes: DNI; PartNumber: ERJ-3GEYJ102V; ROOM: Power
TP1 TP3 TP5 TP6 TP9 TP10 TP15 TP21 TP22 TP24-TP26 TP29 TP32 = T_POINT_R: DNI: DNI; Manuf: Not-a-part; PartNumber: Not-a-part; ROOM: Power
U1 = TPS51100: Manuf: Texas Instruments; PartNumber: TPS51100DGQ; ROOM: Power
U4 = TPS54316PWPG4_0: Manuf: Texas Instruments; PartNumber: TPS54316PWPG4; ROOM: Power
U7 = TPS546_0: Manuf: Texas Instruments; PartNumber: TPS54615PWP; ROOM: Power
U12 = TPS546_0: Manuf: Texas Instruments; PartNumber: TPS54614PWPG4; ROOM: Power
U16 = TPS61081: Manuf: Texas Instruments; PartNumber: TPS61081DRCT; ROOM: Power
U23 = TPS3707-DGNG: Manuf: Texas Instruments; PartNumber: TPS3707-25DGNG4; ROOM: Power
C136 = CAP_NP: Manuf: KEMET; PartNumber: C0603C392J3GAC7867; ROOM: Power; Tolerance: C0G; Voltage: 25V
C138 = CAP_NP: Manuf: TDK; PartNumber: C1608C0G1H101J; ROOM: Power; Tolerance: C0G; Voltage: 50V
C151 = CAP_POL: Manuf: AVX; PartNumber: TAJC227K004RNJ; ROOM: Power; Tolerance: 10%; Voltage: 4V
C285 = CAP_POL: DNI: DNI; Manuf: AVX; Notes: DNI; PartNumber: TPSC475K035R0600; ROOM: Power; Tolerance: 10%; Voltage: 4V
C286 = CAP_NP: Manuf: KEMET; PartNumber: C0603C272J5GAC7867; ROOM: Power; Tolerance: C0G; Voltage: 50V
L9 = INDUCTOR: Irms: 4.4A; Manuf: COILCRAFT; PartNumber: DO1813H-122MLB; RDC: 0.014; ROOM: Power; Tolerance: 20
R103 = R_v2: Manuf: Panasonic; PartNumber: ERJ-3EKF8202V; ROOM: POWER; Tolerance: %1
R104 = R_v2: Manuf: Panasonic; PartNumber: ERJ-3EKF3741V; ROOM: POWER; Tolerance: %1
R106 = R_v2: Manuf: Panasonic; PartNumber: ERJ-3GEYJ103V; ROOM: POWER; Tolerance: %1
R117 R120 = R_v2: Manuf: Stackpole; PartNumber: RMCF1206ZG0R00; ROOM: POWER
R262 = R_v2: Manuf: Panasonic; PartNumber: ERJ-3EKF7320V; ROOM: POWER; Tolerance: %1
R264 = R_v2: Manuf: Panasonic; PartNumber: ERJ-3EKF49R9V; ROOM: POWER; Tolerance: %1
U17 = TPS54310PWP: Manuf: Texas Instruments; ROOM: Power
J5 = CON3: Manuf: Samtec; PartNumber: TSM-103-01-L-SV
J8 J9 = MICTOR19x2: Manuf: AMP; Vendor: AMP
Q5 = MMBTH69L: Current: 200mA; Manuf: Nexperia; TYPE: NPN; VOLTAGE: 15V
R30 R33 R141 = R_v2: Manuf: Panasonic; PartNumber: ERJ-3GEYJ103V; Tolerance: %1
R140 = R_v2: Manuf: Panasonic; PartNumber: ERJ-3GEYJ102V; Tolerance: %1
SH6 = CON2_1: CONN SHUNT SPRING 2POS .100 GOLD; Manuf: AMP; PartNumber: 530153-2
U25 U26 = SN74CB3Q16244: IC BUS SWITCH 4 X 1:1 48TVSOP; Digikey Part Number: 296-19115-1-ND; MFG: Texas Instruments; MFG Part Number: SN74CB3Q16244DGVR; Manuf: Texas Instruments; Manufacturer: Texas Instruments; PartNumber: SN74CB3Q16244DGVR
C9 C12 C18 C19 C24 C25 C159 C161 C201 C212 C213 = CAP_NP: Manuf: Kemet; PartNumber: C0603C104K4RACTU; ROOM: USB; Tolerance: 10%; Voltage: 16V
C21 = CAP_NP: Manuf: TDK; PartNumber: C1608X7R1C105K; ROOM: USB; Tolerance: 10%; Voltage: 16V
C23 = CAP_POL: Manuf: AVX; PartNumber: TAJA106K016RNJ; ROOM: USB; Tolerance: 10%; Voltage: 16V
C154 C163 C164 = CAP_NP: Manuf: TDK; PartNumber: C1005X7R1H102K; ROOM: USB; Tolerance: X7R; Voltage: 50V
C168 C175 = CAP_NP: Manuf: KEMET; PartNumber: C0603C120J5GAC7867; ROOM: USB; Tolerance: C0G; Voltage: 50
D1 = LED: Manuf: ROHM; ROOM: USB
D13 = DIODE_TS: Manuf: Diode Inc; PartNumber: SMAJ6.0A-13-F; Power: 400W; ROOM: USB; Voltage: 6V
D14 = TPD2E001DRLR: Manuf: TI; ROOM: USB
FB8 = INDUCTOR: Current: 3A; Impedance: 60; Manuf: Murata; ROOM: USB
FB12 = DFM-BEAD: Manuf: Laird; ROOM: SODIMM; Vendor: STEWARD
J1 = UX50-MB-5ST: Manuf: Molex; PartNumber: 0548190589; ROOM: USB
J7 = HEADER_2: Manuf: Samtec; PartNumber: TSW-102-07-F-S; ROOM: USB
L10 = CHOKE_CM14: Impedance: 90; Manuf: Murata; ROOM: USB
R3 R20 R22 R25 R26 R28 R32 R35 R143 = R_v2: Manuf: Panasonic; PartNumber: ERJ-3GEYJ472V; ROOM: USB; Tolerance: %1
R10 R139 = R_v2: Manuf: Panasonic; PartNumber: ERJ-3GEYJ103V; ROOM: USB; Tolerance: %1
R11 R17 = R_v2: DNI: DNI; Manuf: Panasonic; Notes: DNI; PartNumber: ERJ-3GEYJ472V; ROOM: USB; Tolerance: %1
R12 R14 R18 R121 R124 R125 R138 R151 = R_v2: Manuf: Panasonic; PartNumber: ERJ-3GEY0R00V; ROOM: USB; Tolerance: %1
R13 R127 = R_v2: Manuf: Panasonic; PartNumber: ERJ-3GEYJ104V; ROOM: USB
R29 = R_v2: Manuf: Panasonic; PartNumber: ERJ-2RKF1000X; ROOM: V5
R34 = R_v2: Manuf: Panasonic; PartNumber: ERJ-3EKF22R1V; ROOM: USB; Tolerance: %1
R129 = R_v2: Manuf: Panasonic; PartNumber: ERJ-3GEYJ203V; ROOM: USB
R137 = R_v2: DNI: DNI; Manuf: Panasonic; Notes: DNI; PartNumber: ERJ-3GEY0R00V; ROOM: USB; Tolerance: %1
R144 R149 = R_v2: Manuf: Panasonic; PartNumber: ERJ-3GEYJ222V; ROOM: USB
R152 = R_v2: DNI: DNI; Manuf: Panasonic; Notes: DNI; PartNumber: ERJ-3GEYJ102V; ROOM: USB
TP8 = T_POINT_R: DNI: DNI; Manuf: Not-a-part; PartNumber: Not-a-part; ROOM: USB
U18 = CY7C68013_128: Manuf: Cypress; ROOM: USB
U19 = EPROM_24LC256: Manuf: ROHM Semiconductor; PartNumber: BR24S128F-WE2; ROOM: USB
Y5 = CRYSTAL: Load Capacitance: 12pF; Manuf: ECS Inc; PartNumber: ECS-240-12-20A-TR; ROOM: USB; Tolerance: +/-30ppm

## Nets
GND: C1.2 C5.2 C7.2 C9.2 C10.2 C11.2 C12.2 C14.2 C18.2 C19.2 C21.2 C23.2 C24.2 C25.2 C36.2 C37.2 C38.2 C39.2 C40.2 C47.2 C58.2 C62.2 C68.2 C70.2 C85.2 C94.2 C95.2 C98.2 C99.2 C103.2 C123.2 C127.2 C129.2 C133.2 C134.2 C135.2 C139.2 C140.2 C142.2 C143.2 C144.2 C145.2 C147.2 C148.2 C151.2 C152.2 C154.1 C159.2 C161.2 C163.2 C164.2 C168.2 C175.2 C180.2 C182.2 C186.2 C187.2 C193.2 C196.2 C201.2 C204.2 C206.2 C207.2 C210.2 C212.2 C213.2 C214.2 C219.2 C230.2 C244.2 C255.2 C258.2 C261.2 C262.2 C269.2 C273.2 C275.2 C276.2 C277.2 C280.2 C283.2 C285.2 C287.2 C289.2 C290.2 D13.2(CATHODE) D14.4(GND) J1.5(GND) J5.1 J8.3 J8.G1(GND1) J8.G2(GND2) J8.G3(GND3) J8.G4(GND4) J8.G5(GND5) J9.3 J9.G1(GND1) J9.G2(GND2) J9.G3(GND3) J9.G4(GND4) J9.G5(GND5) J14.1A(GND1A) J14.1D(GND1D) J14.2C(GND2C) J14.2F(GND2F) J14.3A(GND3A) J14.3D(GND3D) J14.4C(GND4C) J14.4F(GND4F) J14.5A(GND5A) J14.5D(GND5D) J14.6C(GND6C) J14.6F(GND6F) J14.7A(GND7A) J14.7D(GND7D) J14.8C(GND8C) J14.8F(GND8F) J14.9A(GND9A) J14.9D(GND9D) J14.10C(GND10C) J14.10F(GND10F) J14.11A(GND11A) J14.11D(GND11D) J14.12C(GND12C) J14.12F(GND12F) J14.13D(GND13D) J14.14C(GND14C) J14.14F(GND14F) J14.15A(GND15A) J14.15D(GND15D) J14.16C(GND16C) J14.16F(GND16F) J14.17A(GND17A) J14.17D(GND17D) J14.18C(GND18C) J14.18F(GND18F) J14.19A(GND19A) J14.19D(GND19D) J14.20C(GND20C) J14.20F(GND20F) J14.21A(GND21A) J14.21D(GND21D) J14.22C(GND22C) J14.22F(GND22F) J14.23A(GND23A) J14.23D(GND23D) J14.24C(GND24C) J14.24F(GND24F) J14.25A(GND25A) J14.25D(GND25D) J16.45(GND_1) J16.46(GND_2) J16.51(GND_3) J16.52(GND_4) J16.57(GND_5) J16.58(GND_6) J16.63(GND_7) J16.64(GND_8) J16.69(GND_9) J16.70(GND_10) J16.75(GND_11) J16.76(GND_12) J16.121(BGND_1) J16.122(BGND_2) J16.123(BGND_3) J16.124(BGND_4) J16.125(BGND_5) J16.126(BGND_6) J16.127(BGND_7) J16.128(BGND_8) J16.129(BGND_9) J16.130(BGND_10) J16.131(BGND_11) J16.132(BGND_12) J17.45(GND_1) J17.46(GND_2) J17.51(GND_3) J17.52(GND_4) J17.57(GND_5) J17.58(GND_6) J17.63(GND_7) J17.64(GND_8) J17.69(GND_9) J17.70(GND_10) J17.75(GND_11) J17.76(GND_12) J17.121(BGND_1) J17.122(BGND_2) J17.123(BGND_3) J17.124(BGND_4) J17.125(BGND_5) J17.126(BGND_6) J17.127(BGND_7) J17.128(BGND_8) J17.129(BGND_9) J17.130(BGND_10) J17.131(BGND_11) J17.132(BGND_12) Q5.2(EMITTER) R20.2 R22.2 R25.2 R26.2 R28.2 R32.2 R33.1 R35.2 R103.2 R109.1 R111.1 R116.2 R121.2 R127.2 R139.2 R143.1 R151.2 R159.1 R169.1 R227.1 TP1.1(TP) TP5.1(TP) TP22.1(TP) TP24.1(TP) U1.4(PGND) U1.8(GND) U1.11(PPAD) U4.1(AGND) U4.11(PGND1) U4.12(PGND2) U4.13(PGND3) U4.21(THPAD) U7.1(AGND) U7.15(PGND1) U7.16(PGND2) U7.17(PGND3) U7.18(PGND4) U7.19(PGND5) U7.29(THPAD) U12.1(AGND) U12.15(PGND1) U12.16(PGND2) U12.17(PGND3) U12.18(PGND4) U12.19(PGND5) U12.29(THPAD) U16.4(GND) U16.7(FSW) U16.8(PGND) U16.11(TGND) U17.1(AGND) U17.11(PGND1) U17.12(PGND2) U17.13(PGND3) U17.21(THPAD) U18.3(GND_1) U18.13(AGND) U18.20(GND_2) U18.27(GND_3) U18.33(RSVD) U18.49(GND_4) U18.58(GND_5) U18.65(GND_6) U18.80(GND_7) U18.93(GND_8) U18.116(GND_9) U18.125(GND_10) U19.3(A2) U19.4(GND) U23.5(GND) U23.9(THPAD) U25.4(GND) U25.10(GND) U25.15(GND) U25.21(GND) U25.28(GND) U25.34(GND) U25.39(GND) U25.45(GND) U26.4(GND) U26.10(GND) U26.15(GND) U26.21(GND) U26.28(GND) U26.34(GND) U26.39(GND) U26.45(GND) ; also on sheet 4 6 7 8 9 10 11 12 13 14 15
GND_EARTH: C154.2 D13.1(ANODE) J1.6(S1) J1.7(S2) J1.8(S3) J1.9(S4) R121.1
VCC_1P0V: R120.2 TP32.1(TP) ; also on sheet 8
VCC_1P0V_DDC: C285.1 R117.2 TP29.1(TP) ; also on sheet 12
VCC_1P8V: C5.1 R91.2 TP25.1(TP) U1.1(VDDQSNS) U1.2(VLDOIN) ; also on sheet 4 6 8 9 12
VCC_2P5V: C17.1 C22.1 C29.1 C33.1 C35.1 C73.1 C81.1 C90.1 C91.1 C97.1 C117.1 C118.1 C244.1 R42.1 R43.1 R61.2 TP10.1(TP) ; also on sheet 4 5 6 7 8 10 11 12 13 14
VCC_2P5V_EXP1: C186.1 C187.1 C196.1 C204.1 C210.1 J16.5(2.5V_1) J16.6(2.5V_2) J16.11(2.5V_3) J16.12(2.5V_4) J16.17(2.5V_5) J16.18(2.5V_6) J16.23(2.5V_7) J16.24(2.5V_8) J16.29(2.5V_9) J16.30(2.5V_10) J16.35(2.5V_11) J16.36(2.5V_12) R42.2
VCC_2P5V_EXP2: C180.1 C182.1 C193.1 C206.1 C207.1 J17.5(2.5V_1) J17.6(2.5V_2) J17.11(2.5V_3) J17.12(2.5V_4) J17.17(2.5V_5) J17.18(2.5V_6) J17.23(2.5V_7) J17.24(2.5V_8) J17.29(2.5V_9) J17.30(2.5V_10) J17.35(2.5V_11) J17.36(2.5V_12) R43.2
VCC_3P3V: C17.2 C18.1 C19.1 C22.2 C23.1 C24.1 C25.1 C29.2 C33.2 C35.2 C36.1 C73.2 C81.2 C90.2 C91.2 C97.2 C117.2 C118.2 C127.1 C135.1 C159.1 C161.1 C201.1 C212.1 C213.1 C214.1 C219.1 C289.1 C290.1 D1.1(ANODE) FB4.1 FB5.1 FB12.2 J7.1 R3.2 R10.1 R11.2 R13.1 R17.2 R30.2 R41.2 R78.1 R80.1 R141.2 R144.2 R149.2 R152.2 TP9.1(TP) U18.2(VCC_1) U18.26(VCC_3) U18.43(VCC_4) U18.48(VCC_5) U18.64(VCC_6) U18.68(VCC_7) U18.81(VCC_8) U18.100(VCC_9) U18.107(VCC_10) U19.1(A0) U19.8(VCC) U25.7(VCC) U25.18(VCC) U25.31(VCC) U25.42(VCC) U26.7(VCC) U26.18(VCC) U26.31(VCC) U26.42(VCC) ; also on sheet 4 5 6 7 8 9 12 15
VCC_3P3V_EXP1: C258.1 C261.1 C273.1 C275.1 C277.1 J16.85(3.3V_1) J16.86(3.3V_2) J16.91(3.3V_3) J16.92(3.3V_4) J16.97(3.3V_5) J16.98(3.3V_6) J16.103(3.3V_7) J16.104(3.3V_8) J16.109(3.3V_9) J16.110(3.3V_10) J16.115(3.3V_11) J16.116(3.3V_12) R80.2
VCC_3P3V_EXP2: C255.1 C262.1 C269.1 C276.1 C280.1 J17.85(3.3V_1) J17.86(3.3V_2) J17.91(3.3V_3) J17.92(3.3V_4) J17.97(3.3V_5) J17.98(3.3V_6) J17.103(3.3V_7) J17.104(3.3V_8) J17.109(3.3V_9) J17.110(3.3V_10) J17.115(3.3V_11) J17.116(3.3V_12) R78.2
VCC_5P0V: C10.1 C39.1 C47.1 C68.1 C70.1 C98.1 C99.1 C142.1 C147.1 C230.1 C287.1 R31.1 R102.1 R160.1 U1.7(S3) U1.9(S5) U1.10(VIN) U4.14(VIN1) U4.15(VIN2) U4.16(VIN3) U4.19(FSEL) U7.20(VIN1) U7.21(VIN2) U7.22(VIN3) U7.23(VIN4) U7.24(VIN5) U7.27(FSEL) U12.20(VIN1) U12.21(VIN2) U12.22(VIN3) U12.23(VIN4) U12.24(VIN5) U12.27(FSEL) U16.2(VIN) U16.6(EN) U17.14(VIN1) U17.15(VIN2) U17.16(VIN3) U23.4(VDD) ; also on sheet 4
VCC_12V: R110.2 TP21.1(TP) ; also on sheet 13 14
VCC_VREF: R4.2 TP3.1(TP) ; also on sheet 6 9
DDC_DCLKOUT_C_DPN: J14.5C(DCLKAN) ; also on sheet 11
DDC_DCLKOUT_C_DPP: J14.5B(DCLKAP) ; also on sheet 11
DDC_DCLKOUT_D_DPN: J14.21C(DCLKBN) ; also on sheet 11
DDC_DCLKOUT_D_DPP: J14.21B(DCLKBP) ; also on sheet 11
DDC_DOUT_C0_DPN: J14.10E(DDAN0) ; also on sheet 11
DDC_DOUT_C0_DPP: J14.10D(DDAP0) ; also on sheet 11
DDC_DOUT_C1_DPN: J14.9C(DDAN1) ; also on sheet 11
DDC_DOUT_C1_DPP: J14.9B(DDAP1) ; also on sheet 11
DDC_DOUT_C2_DPN: J14.9F(DDAN2) ; also on sheet 11
DDC_DOUT_C2_DPP: J14.9E(DDAP2) ; also on sheet 11
DDC_DOUT_C3_DPN: J14.8B(DDAN3) ; also on sheet 11
DDC_DOUT_C3_DPP: J14.8A(DDAP3) ; also on sheet 11
DDC_DOUT_C4_DPN: J14.8E(DDAN4) ; also on sheet 11
DDC_DOUT_C4_DPP: J14.8D(DDAP4) ; also on sheet 11
DDC_DOUT_C5_DPN: J14.7C(DDAN5) ; also on sheet 11
DDC_DOUT_C5_DPP: J14.7B(DDAP5) ; also on sheet 11
DDC_DOUT_C6_DPN: J14.7F(DDAN6) ; also on sheet 11
DDC_DOUT_C6_DPP: J14.7E(DDAP6) ; also on sheet 11
DDC_DOUT_C7_DPN: J14.6B(DDAN7) ; also on sheet 11
DDC_DOUT_C7_DPP: J14.6A(DDAP7) ; also on sheet 11
DDC_DOUT_C8_DPN: J14.5F(DDAN8) ; also on sheet 11
DDC_DOUT_C8_DPP: J14.5E(DDAP8) ; also on sheet 11
DDC_DOUT_C9_DPN: J14.4B(DDAN9) ; also on sheet 11
DDC_DOUT_C9_DPP: J14.4A(DDAP9) ; also on sheet 11
DDC_DOUT_C10_DPN: J14.4E(DDAN10) ; also on sheet 11
DDC_DOUT_C10_DPP: J14.4D(DDAP10) ; also on sheet 11
DDC_DOUT_C11_DPN: J14.3C(DDAN11) ; also on sheet 11
DDC_DOUT_C11_DPP: J14.3B(DDAP11) ; also on sheet 11
DDC_DOUT_C12_DPN: J14.3F(DDAN12) ; also on sheet 11
DDC_DOUT_C12_DPP: J14.3E(DDAP12) ; also on sheet 11
DDC_DOUT_C13_DPN: J14.2B(DDAN13) ; also on sheet 11
DDC_DOUT_C13_DPP: J14.2A(DDAP13) ; also on sheet 11
DDC_DOUT_C14_DPN: J14.2E(DDAN14) ; also on sheet 11
DDC_DOUT_C14_DPP: J14.2D(DDAP14) ; also on sheet 11
DDC_DOUT_C15_DPN: J14.1F(DDAN15) ; also on sheet 11
DDC_DOUT_C15_DPP: J14.1E(DDAP15) ; also on sheet 11
DDC_DOUT_D0_DPN: J14.16E(DDBN0) ; also on sheet 11
DDC_DOUT_D0_DPP: J14.16D(DDBP0) ; also on sheet 11
DDC_DOUT_D1_DPN: J14.17C(DDBN1) ; also on sheet 11
DDC_DOUT_D1_DPP: J14.17B(DDBP1) ; also on sheet 11
DDC_DOUT_D2_DPN: J14.17F(DDBN2) ; also on sheet 11
DDC_DOUT_D2_DPP: J14.17E(DDBP2) ; also on sheet 11
DDC_DOUT_D3_DPN: J14.18B(DDBN3) ; also on sheet 11
DDC_DOUT_D3_DPP: J14.18A(DDBP3) ; also on sheet 11
DDC_DOUT_D4_DPN: J14.18E(DDBN4) ; also on sheet 11
DDC_DOUT_D4_DPP: J14.18D(DDBP4) ; also on sheet 11
DDC_DOUT_D5_DPN: J14.19C(DDBN5) ; also on sheet 11
DDC_DOUT_D5_DPP: J14.19B(DDBP5) ; also on sheet 11
DDC_DOUT_D6_DPN: J14.19F(DDBN6) ; also on sheet 11
DDC_DOUT_D6_DPP: J14.19E(DDBP6) ; also on sheet 11
DDC_DOUT_D7_DPN: J14.20B(DDBN7) ; also on sheet 11
DDC_DOUT_D7_DPP: J14.20A(DDBP7) ; also on sheet 11
DDC_DOUT_D8_DPN: J14.21F(DDBN8) ; also on sheet 11
DDC_DOUT_D8_DPP: J14.21E(DDBP8) ; also on sheet 11
DDC_DOUT_D9_DPN: J14.22B(DDBN9) ; also on sheet 11
DDC_DOUT_D9_DPP: J14.22A(DDBP9) ; also on sheet 11
DDC_DOUT_D10_DPN: J14.22E(DDBN10) ; also on sheet 11
DDC_DOUT_D10_DPP: J14.22D(DDBP10) ; also on sheet 11
DDC_DOUT_D11_DPN: J14.23C(DDBN11) ; also on sheet 11
DDC_DOUT_D11_DPP: J14.23B(DDBP11) ; also on sheet 11
DDC_DOUT_D12_DPN: J14.23F(DDBN12) ; also on sheet 11
DDC_DOUT_D12_DPP: J14.23E(DDBP12) ; also on sheet 11
DDC_DOUT_D13_DPN: J14.24B(DDBN13) ; also on sheet 11
DDC_DOUT_D13_DPP: J14.24A(DDBP13) ; also on sheet 11
DDC_DOUT_D14_DPN: J14.24E(DDBN14) ; also on sheet 11
DDC_DOUT_D14_DPP: J14.24D(DDBP14) ; also on sheet 11
DDC_DOUT_D15_DPN: J14.25C(DDBN15) ; also on sheet 11
DDC_DOUT_D15_DPP: J14.25B(DDBP15) ; also on sheet 11
DDC_SCTRL_CN: J14.6E(SCTRLAN) ; also on sheet 11
DDC_SCTRL_CP: J14.6D(SCTRLAP) ; also on sheet 11
DDC_SCTRL_DN: J14.20E(SCTRLBN) ; also on sheet 11
DDC_SCTRL_DP: J14.20D(SCTRLBP) ; also on sheet 11
DDR2_SCL: R11.1 R12.2 ; also on sheet 5 9
DDR2_SDA: R17.1 R18.2 ; also on sheet 5 9
DMD_B_RESET: R258.1 ; also on sheet 11
DMD_B_RESET_FILT: C283.1 J14.11F(DMDRSTZ) R258.2
DMD_B_SCPCLK_FILT: C129.1 J14.10B(SCPCLK) R97.2
DMD_B_SCPDO_FILT: C123.1 J14.10A(SCPD0) R71.2
DMD_B_SCPENZ: R99.1 ; also on sheet 11
DMD_B_SCPENZ_FILT: C134.1 J14.11C(DMDSELZ) R99.2
DMDSPARE2: J14.11B(DMDSPARE1) R111.2 TP19.1(TP)
DMDSPARE3: J14.12D(DMDSPARE0) R109.2 TP23.1(TP)
ECP2_M_TP0: J8.2 ; also on sheet 11
ECP2_M_TP1: J8.4 ; also on sheet 11
ECP2_M_TP2: J8.6 ; also on sheet 11
ECP2_M_TP3: J8.8 ; also on sheet 11
ECP2_M_TP4: J8.10 ; also on sheet 11
ECP2_M_TP5: J8.12 ; also on sheet 11
ECP2_M_TP6: J8.14 ; also on sheet 11
ECP2_M_TP7: J8.16 ; also on sheet 11
ECP2_M_TP8: J8.18 ; also on sheet 11 12
ECP2_M_TP9: J8.20 ; also on sheet 11
ECP2_M_TP10: J8.22 ; also on sheet 11
ECP2_M_TP11: J8.24 ; also on sheet 11 12
ECP2_M_TP12: J8.26 ; also on sheet 11
ECP2_M_TP13: J8.28 ; also on sheet 11
ECP2_M_TP14: J8.30 ; also on sheet 11
ECP2_M_TP15: J8.32 ; also on sheet 11
ECP2_M_TP16: J8.34 ; also on sheet 11
ECP2_M_TP17: J8.36 ; also on sheet 11
ECP2_M_TP18: J8.38 ; also on sheet 11
ECP2_M_TP19: J8.37 ; also on sheet 11
ECP2_M_TP20: J8.35 ; also on sheet 11
ECP2_M_TP21: J8.33 ; also on sheet 11
ECP2_M_TP22: J8.31 ; also on sheet 11
ECP2_M_TP23: J8.29 ; also on sheet 11
ECP2_M_TP24: J8.27 ; also on sheet 11
ECP2_M_TP25: J8.25 ; also on sheet 11
ECP2_M_TP26: J8.23 ; also on sheet 11
ECP2_M_TP27: J8.21 ; also on sheet 11
ECP2_M_TP28: J8.19 ; also on sheet 11
ECP2_M_TP29: J8.17 ; also on sheet 11
ECP2_M_TP30: J8.15 ; also on sheet 11
ECP2_M_TP31: J8.13 ; also on sheet 11
EXP1_DIFF_0_N: J16.120(DIFF_0_N) ; also on sheet 5
EXP1_DIFF_0_P: J16.118(DIFF_0_P) ; also on sheet 5
EXP1_DIFF_1_N: J16.119(DIFF_1_N) ; also on sheet 5
EXP1_DIFF_1_P: J16.117(DIFF_1_P) ; also on sheet 5
EXP1_DIFF_2_N: J16.114(DIFF_2_N) ; also on sheet 5
EXP1_DIFF_2_P: J16.112(DIFF_2_P) ; also on sheet 5
EXP1_DIFF_3_N: J16.113(DIFF_3_N) ; also on sheet 5
EXP1_DIFF_3_P: J16.111(DIFF_3_P) ; also on sheet 5
EXP1_DIFF_4_N: J16.108(DIFF_4_N) ; also on sheet 5
EXP1_DIFF_4_P: J16.106(DIFF_4_P) ; also on sheet 5
EXP1_DIFF_5_N: J16.107(DIFF_5_N) ; also on sheet 5
EXP1_DIFF_5_P: J16.105(DIFF_5_P) ; also on sheet 5
EXP1_DIFF_6_N: J16.102(DIFF_6_N) ; also on sheet 5
EXP1_DIFF_6_P: J16.100(DIFF_6_P) ; also on sheet 5
EXP1_DIFF_7_N: J16.101(DIFF_7_N) ; also on sheet 5
EXP1_DIFF_7_P: J16.99(DIFF_7_P) ; also on sheet 5
EXP1_DIFF_8_N: J16.96(DIFF_8_N) ; also on sheet 5
EXP1_DIFF_8_P: J16.94(DIFF_8_P) ; also on sheet 5
EXP1_DIFF_9_N: J16.95(DIFF_9_N) ; also on sheet 5
EXP1_DIFF_9_P: J16.93(DIFF_9_P) ; also on sheet 5
EXP1_DIFF_10_N: J16.90(DIFF_10_N) ; also on sheet 5
EXP1_DIFF_10_P: J16.88(DIFF_10_P) ; also on sheet 5
EXP1_DIFF_11_N: J16.89(DIFF_11_N) ; also on sheet 5
EXP1_DIFF_11_P: J16.87(DIFF_11_P) ; also on sheet 5
EXP1_DIFF_12_N: J16.84(DIFF_12_N) ; also on sheet 5
EXP1_DIFF_12_P: J16.82(DIFF_12_P) ; also on sheet 5
EXP1_DIFF_13_N: J16.83(DIFF_13_N) ; also on sheet 5
EXP1_DIFF_13_P: J16.81(DIFF_13_P) ; also on sheet 5
EXP1_DIFF_14_N: J16.80(DIFF_14_N) ; also on sheet 5
EXP1_DIFF_14_P: J16.78(DIFF_14_P) ; also on sheet 5
EXP1_DIFF_15_N: J16.79(DIFF_15_N) ; also on sheet 5
EXP1_DIFF_15_P: J16.77(DIFF_15_P) ; also on sheet 5
EXP1_DIFF_16_N: J16.68(DIFF_16_N) ; also on sheet 5
EXP1_DIFF_16_P: J16.66(DIFF_16_P) ; also on sheet 5
EXP1_DIFF_17_N: J16.73(DIFF_17_N) ; also on sheet 5
EXP1_DIFF_17_P: J16.71(DIFF_17_P) ; also on sheet 5
EXP1_DIFF_18_N: J16.62(DIFF_18_N) ; also on sheet 5
EXP1_DIFF_18_P: J16.60(DIFF_18_P) ; also on sheet 5
EXP1_DIFF_19_N: J16.67(DIFF_19_N) ; also on sheet 5
EXP1_DIFF_19_P: J16.65(DIFF_19_P) ; also on sheet 5
EXP1_DIFF_20_N: J16.56(MGT_2_DIFF_20_N) ; also on sheet 5
EXP1_DIFF_20_P: J16.54(MGT_2_DIFF_20_P) ; also on sheet 5
EXP1_DIFF_21_N: J16.55(MGT_2_DIFF_21_N) ; also on sheet 5
EXP1_DIFF_21_P: J16.53(MGT_2_DIFF_21_P) ; also on sheet 5
EXP1_DIFF_CLK_IN_DPN: J16.44(DIFF_CLK_IN_N) ; also on sheet 7
EXP1_DIFF_CLK_IN_DPP: J16.42(DIFF_CLK_IN_P) ; also on sheet 7
EXP1_DIFF_CLK_OUT_N: J16.74(DIFF_CLK_OUT_N) ; also on sheet 5
EXP1_DIFF_CLK_OUT_P: J16.72(DIFF_CLK_OUT_P) ; also on sheet 5
EXP1_SE_CLK_IN: J16.43(SE_CLK_IN) ; also on sheet 7
EXP1_SE_CLK_OUT: J16.49(SE_CLK_OUT) ; also on sheet 7
EXP1_SE_IO_0: J16.2(SE_IO_0) ; also on sheet 5
EXP1_SE_IO_1: J16.1(SE_IO) ; also on sheet 5
EXP1_SE_IO_2: J16.4(SE_IO_2) ; also on sheet 5
EXP1_SE_IO_3: J16.3(SE_IO) ; also on sheet 5
EXP1_SE_IO_4: J16.8(SE_IO_4) ; also on sheet 5
EXP1_SE_IO_5: J16.7(SE_IO_5) ; also on sheet 5
EXP1_SE_IO_6: J16.10(SE_IO_6) ; also on sheet 5
EXP1_SE_IO_7: J16.9(SE_IO_7) ; also on sheet 5
EXP1_SE_IO_8: J16.14(SE_IO_8) ; also on sheet 5
EXP1_SE_IO_9: J16.13(SE_IO_9) ; also on sheet 5
EXP1_SE_IO_10: J16.16(SE_IO_10) ; also on sheet 5
EXP1_SE_IO_11: J16.15(SE_IO_11) ; also on sheet 5
EXP1_SE_IO_12_DIFF_22_P: J16.20(SE_IO_12) ; also on sheet 5
EXP1_SE_IO_13_DIFF_23_P: J16.19(SE_IO_13) ; also on sheet 5
EXP1_SE_IO_14_DIFF_22_N: J16.22(SE_IO_14) ; also on sheet 5
EXP1_SE_IO_15_DIFF_23_N: J16.21(SE_IO_15) ; also on sheet 5
EXP1_SE_IO_16_DIFF_24_P: J16.26(SE_IO_16) ; also on sheet 5
EXP1_SE_IO_17_DIFF_25_P: J16.25(SE_IO_17) ; also on sheet 5
EXP1_SE_IO_18_DIFF_24_N: J16.28(SE_IO_18) ; also on sheet 5
EXP1_SE_IO_19_DIFF_25_N: J16.27(SE_IO_19) ; also on sheet 5
EXP1_SE_IO_20_DIFF_26_P: J16.32(SE_IO_20) ; also on sheet 5
EXP1_SE_IO_21_DIFF_27_P: J16.31(SE_IO_21) ; also on sheet 5
EXP1_SE_IO_22_DIFF_26_N: J16.34(SE_IO_22) ; also on sheet 5
EXP1_SE_IO_23_DIFF_27_N: J16.33(SE_IO_23) ; also on sheet 5
EXP1_SE_IO_24_DIFF_28_P: J16.38(SE_IO_24) ; also on sheet 5
EXP1_SE_IO_25_DIFF_29_P: J16.37(SE_IO_25) ; also on sheet 5
EXP1_SE_IO_26_DIFF_28_N: J16.40(SE_IO_26) ; also on sheet 5
EXP1_SE_IO_27_DIFF_29_N: J16.39(SE_IO_27) ; also on sheet 5
EXP1_SE_IO_28: J16.41(SE_IO_28) ; also on sheet 5
EXP1_SE_IO_29: J16.47(SE_IO_29) ; also on sheet 5
EXP1_SE_IO_30_DIFF_30_P: J16.48(SE_IO_30) ; also on sheet 5
EXP1_SE_IO_31_DIFF_30_N: J16.50(SE_IO_31) ; also on sheet 5
EXP1_SE_IO_32_DIFF_31_P: J16.59(SE_IO_32) ; also on sheet 5
EXP1_SE_IO_33_DIFF_31_N: J16.61(SE_IO_33) ; also on sheet 5
EXP2_DIFF_0_N: J17.120(DIFF_0_N) ; also on sheet 5
EXP2_DIFF_0_P: J17.118(DIFF_0_P) ; also on sheet 5
EXP2_DIFF_1_N: J17.119(DIFF_1_N) ; also on sheet 5
EXP2_DIFF_1_P: J17.117(DIFF_1_P) ; also on sheet 5
EXP2_DIFF_2_N: J17.114(DIFF_2_N) ; also on sheet 5
EXP2_DIFF_2_P: J17.112(DIFF_2_P) ; also on sheet 5
EXP2_DIFF_3_N: J17.113(DIFF_3_N) ; also on sheet 5
EXP2_DIFF_3_P: J17.111(DIFF_3_P) ; also on sheet 5
EXP2_DIFF_4_N: J17.108(DIFF_4_N) ; also on sheet 5
EXP2_DIFF_4_P: J17.106(DIFF_4_P) ; also on sheet 5
EXP2_DIFF_5_N: J17.107(DIFF_5_N) ; also on sheet 5
EXP2_DIFF_5_P: J17.105(DIFF_5_P) ; also on sheet 5
EXP2_DIFF_6_N: J17.102(DIFF_6_N) ; also on sheet 5
EXP2_DIFF_6_P: J17.100(DIFF_6_P) ; also on sheet 5
EXP2_DIFF_7_N: J17.101(DIFF_7_N) ; also on sheet 5
EXP2_DIFF_7_P: J17.99(DIFF_7_P) ; also on sheet 5
EXP2_DIFF_8_N: J17.96(DIFF_8_N) ; also on sheet 5
EXP2_DIFF_8_P: J17.94(DIFF_8_P) ; also on sheet 5
EXP2_DIFF_9_N: J17.95(DIFF_9_N) ; also on sheet 5
EXP2_DIFF_9_P: J17.93(DIFF_9_P) ; also on sheet 5
EXP2_DIFF_10_N: J17.90(DIFF_10_N) ; also on sheet 5
EXP2_DIFF_10_P: J17.88(DIFF_10_P) ; also on sheet 5
EXP2_DIFF_11_N: J17.89(DIFF_11_N) ; also on sheet 5
EXP2_DIFF_11_P: J17.87(DIFF_11_P) ; also on sheet 5
EXP2_DIFF_12_N: J17.84(DIFF_12_N) ; also on sheet 5
EXP2_DIFF_12_P: J17.82(DIFF_12_P) ; also on sheet 5
EXP2_DIFF_13_N: J17.83(DIFF_13_N) ; also on sheet 5
EXP2_DIFF_13_P: J17.81(DIFF_13_P) ; also on sheet 5
EXP2_DIFF_14_N: J17.80(DIFF_14_N) ; also on sheet 5
EXP2_DIFF_14_P: J17.78(DIFF_14_P) ; also on sheet 5
EXP2_DIFF_15_N: J17.79(DIFF_15_N) ; also on sheet 5
EXP2_DIFF_15_P: J17.77(DIFF_15_P) ; also on sheet 5
EXP2_DIFF_16_N: J17.68(DIFF_16_N) ; also on sheet 5
EXP2_DIFF_16_P: J17.66(DIFF_16_P) ; also on sheet 5
EXP2_DIFF_17_N: J17.73(DIFF_17_N) ; also on sheet 5
EXP2_DIFF_17_P: J17.71(DIFF_17_P) ; also on sheet 5
EXP2_DIFF_18_N: J17.62(DIFF_18_N) ; also on sheet 5
EXP2_DIFF_18_P: J17.60(DIFF_18_P) ; also on sheet 5
EXP2_DIFF_19_N: J17.67(DIFF_19_N) ; also on sheet 5
EXP2_DIFF_19_P: J17.65(DIFF_19_P) ; also on sheet 5
EXP2_DIFF_20_N: J17.56(MGT_2_DIFF_20_N) ; also on sheet 5
EXP2_DIFF_20_P: J17.54(MGT_2_DIFF_20_P) ; also on sheet 5
EXP2_DIFF_21_N: J17.55(MGT_2_DIFF_21_N) ; also on sheet 5
EXP2_DIFF_21_P: J17.53(MGT_2_DIFF_21_P) ; also on sheet 5
EXP2_DIFF_CLK_IN_DPN: J17.44(DIFF_CLK_IN_N) ; also on sheet 7
EXP2_DIFF_CLK_IN_DPP: J17.42(DIFF_CLK_IN_P) ; also on sheet 7
EXP2_DIFF_CLK_OUT_N: J17.74(DIFF_CLK_OUT_N) ; also on sheet 5
EXP2_DIFF_CLK_OUT_P: J17.72(DIFF_CLK_OUT_P) ; also on sheet 5
EXP2_SE_CLK_IN: J17.43(SE_CLK_IN) ; also on sheet 7
EXP2_SE_CLK_OUT: J17.49(SE_CLK_OUT) ; also on sheet 7
EXP2_SE_IO_0: J17.2(SE_IO_0) ; also on sheet 5
EXP2_SE_IO_1: J17.1(SE_IO) ; also on sheet 5
EXP2_SE_IO_2: J17.4(SE_IO_2) ; also on sheet 5
EXP2_SE_IO_3: J17.3(SE_IO) ; also on sheet 5
EXP2_SE_IO_4: J17.8(SE_IO_4) ; also on sheet 5
EXP2_SE_IO_5: J17.7(SE_IO_5) ; also on sheet 5
EXP2_SE_IO_6: J17.10(SE_IO_6) ; also on sheet 5
EXP2_SE_IO_7: J17.9(SE_IO_7) ; also on sheet 5
EXP2_SE_IO_8: J17.14(SE_IO_8) ; also on sheet 5
EXP2_SE_IO_9: J17.13(SE_IO_9) ; also on sheet 5
EXP2_SE_IO_10: J17.16(SE_IO_10) ; also on sheet 5
EXP2_SE_IO_11: J17.15(SE_IO_11) ; also on sheet 5
EXP2_SE_IO_12_DIFF_22_P: J17.20(SE_IO_12) ; also on sheet 5
EXP2_SE_IO_13_DIFF_23_P: J17.19(SE_IO_13) ; also on sheet 5
EXP2_SE_IO_14_DIFF_22_N: J17.22(SE_IO_14) ; also on sheet 5
EXP2_SE_IO_15_DIFF_23_N: J17.21(SE_IO_15) ; also on sheet 5
EXP2_SE_IO_16_DIFF_24_P: J17.26(SE_IO_16) ; also on sheet 5
EXP2_SE_IO_17_DIFF_25_P: J17.25(SE_IO_17) ; also on sheet 5
EXP2_SE_IO_18_DIFF_24_N: J17.28(SE_IO_18) ; also on sheet 5
EXP2_SE_IO_19_DIFF_25_N: J17.27(SE_IO_19) ; also on sheet 5
EXP2_SE_IO_20_DIFF_26_P: J17.32(SE_IO_20) ; also on sheet 5
EXP2_SE_IO_21_DIFF_27_P: J17.31(SE_IO_21) ; also on sheet 5
EXP2_SE_IO_22_DIFF_26_N: J17.34(SE_IO_22) ; also on sheet 5
EXP2_SE_IO_23_DIFF_27_N: J17.33(SE_IO_23) ; also on sheet 5
EXP2_SE_IO_24_DIFF_28_P: J17.38(SE_IO_24) ; also on sheet 5
EXP2_SE_IO_25_DIFF_29_P: J17.37(SE_IO_25) ; also on sheet 5
EXP2_SE_IO_26_DIFF_28_N: J17.40(SE_IO_26) ; also on sheet 5
EXP2_SE_IO_27_DIFF_29_N: J17.39(SE_IO_27) ; also on sheet 5
EXP2_SE_IO_28: J17.41(SE_IO_28) ; also on sheet 5
EXP2_SE_IO_29: J17.47(SE_IO_29) ; also on sheet 5
EXP2_SE_IO_30_DIFF_30_P: J17.48(SE_IO_30) ; also on sheet 5
EXP2_SE_IO_31_DIFF_30_N: J17.50(SE_IO_31) ; also on sheet 5
EXP2_SE_IO_32_DIFF_31_P: J17.59(SE_IO_32) ; also on sheet 5
EXP2_SE_IO_33_DIFF_31_N: J17.61(SE_IO_33) ; also on sheet 5
FX2_SCL: R12.1 R144.1 U18.36(SCL) U19.6(SCL)
FX2_SDA: R18.1 R149.1 U18.37(SDA) U19.5(SDA)
GPIFADR0: U18.72(PC0/GPIFADR0) U26.47(1A1)
GPIFADR0/TST_HDR_BY2_0: J9.8 U26.2(1B1) ; also on sheet 5
GPIFADR1: U18.73(PC1/GPIFADR1) U26.46(1A2)
GPIFADR1/TST_HDR_BY2_1: J9.10 U26.3(1B2) ; also on sheet 5
GPIFADR2: U18.74(PC2/GPIFADR2) U26.44(1A3)
GPIFADR2/TST_HDR_BY2_2: J9.12 U26.5(1B3) ; also on sheet 5
GPIFADR3: U18.75(PC3/GPIFADR3) U26.43(1A4)
GPIFADR3/TST_HDR_BY2_3: J9.14 U26.6(1B4) ; also on sheet 5
GPIFADR4: U18.76(PC4/GPIFADR4) U26.41(2A1)
GPIFADR4/TST_HDR_BY2_4: J9.16 U26.8(2B1) ; also on sheet 5
GPIFADR5: U18.77(PC5/GPIFADR5) U26.40(2A2)
GPIFADR5/TST_HDR_BY2_5: J9.18 U26.9(2B2) ; also on sheet 5
GPIFADR6: U18.78(PC6/GPIFADR6) U26.38(2A3)
GPIFADR6/TST_HDR_BY2_6: J9.20 U26.11(2B3) ; also on sheet 5
GPIFADR7: U18.79(PC7/GPIFADR7) U26.37(2A4)
GPIFADR7/TST_HDR_BY2_7: J9.22 U26.12(2B4) ; also on sheet 5
GPIFADR8: U18.115(PE7) U26.36(3A1)
GPIFADR8/TST_HDR_BY3_0: J9.24 U26.13(3B1) ; also on sheet 5
MBRST2_0: J14.14D(MBRST0) ; also on sheet 14
MBRST2_1: J14.13C(MBRST1) ; also on sheet 14
MBRST2_2: J14.15E(MBRST2) ; also on sheet 14
MBRST2_3: J14.14E(MBRST3) ; also on sheet 14
MBRST2_4: J14.13F(MBRST4) ; also on sheet 14
MBRST2_5: J14.13E(MBRST5) ; also on sheet 14
MBRST2_6: J14.14B(MBRST6) ; also on sheet 14
MBRST2_7: J14.15C(MBRST7) ; also on sheet 14
MBRST2_8: J14.15F(MBRST8) ; also on sheet 14
MBRST2_9: J14.15B(MBRST9) ; also on sheet 14
MBRST2_10: J14.14A(MBRST10) ; also on sheet 14
MBRST2_11: J14.12E(MBRST11) ; also on sheet 14
MBRST2_12: J14.16B(MBRST12) ; also on sheet 14
MBRST2_13: J14.16A(MBRST13) ; also on sheet 14
MBRST2_14: J14.12B(MBRST14) ; also on sheet 14
MBRST2_15: J14.12A(MBRST15) ; also on sheet 14
POWER_STANDBY#: C140.1 TP26.1(TP) U17.18(SS_ENA) U23.3(~{MR}) ; also on sheet 4
PWRGD: R159.2 R168.1 TP15.1(TP) ; also on sheet 11
PWRGD_1P0: C58.1 C94.1 R102.2 U7.26(SS_ENA) U12.26(SS_ENA) U17.4(PWRGD)
PWRGD_2P5: C38.1 R31.2 U4.18(SS_ENA) U7.4(PWRGD)
RESET: R227.2 R228.1 TP6.1(TP) ; also on sheet 7
RESET_5V: R228.2 U23.2(RESET)
SCPCLK: R97.1 ; also on sheet 11 13 14 15
SCPDI: J14.11E(SCP0_DI) ; also on sheet 11 13 14 15
SCPDO: R71.1 ; also on sheet 11 13 14 15
USB_5P0V: C164.1 FB8.2 R129.1 R140.1
USB_A_3P3V: C9.1 C12.1 FB12.1 U18.10(AVCC) U18.17(AVCC_2)
USB_CFG_SEL: R29.2 U18.82(PA0/INT0#) ; also on sheet 8
USB_CONNECTED#: J5.3 Q5.3(COLLECTOR) R141.1
USB_CTRL0: U18.69(CTL0/FLAGA) U26.35(3A2)
USB_CTRL0/TST_HDR_BY3_1: J9.26 U26.14(3B2) ; also on sheet 5
USB_CTRL1: U18.70(CTL1/FLAGB) U26.33(3A3)
USB_CTRL1/TST_HDR_BY3_2: J9.28 U26.16(3B3) ; also on sheet 5
USB_CTRL2: U18.71(CTL2/FLAGC) U26.32(3A4)
USB_CTRL2/TST_HDR_BY3_3: J9.30 U26.17(3B4) ; also on sheet 5
USB_CTRL3: U18.66(CTL3) U26.30(4A1)
USB_CTRL3/TST_HDR_BY3_4: J9.32 U26.19(4B1) ; also on sheet 5
USB_DPN: R124.2 U18.19(DMINUS)
USB_DPP: R125.2 U18.18(DPLUS)
USB_EXT_DPN: D14.3(IO1) J1.2(D-) L10.4
USB_EXT_DPP: D14.5(IO2) J1.3(D+) L10.1
USB_F_DPN: L10.3 R124.1
USB_F_DPP: L10.2 R125.1
USB_FD0: U18.44(PB0/FD0) U25.47(1A1)
USB_FD0/TST_HDR_BY0_0: J9.7 U25.2(1B1) ; also on sheet 5
USB_FD1: U18.45(PB1/FD1) U25.46(1A2)
USB_FD1/TST_HDR_BY0_1: J9.9 U25.3(1B2) ; also on sheet 5
USB_FD2: U18.46(PB2/FD2) U25.44(1A3)
USB_FD2/TST_HDR_BY0_2: J9.11 U25.5(1B3) ; also on sheet 5
USB_FD3: U18.47(PB3/FD3) U25.43(1A4)
USB_FD3/TST_HDR_BY0_3: J9.13 U25.6(1B4) ; also on sheet 5
USB_FD4: U18.54(PB4/FD4) U25.41(2A1)
USB_FD4/TST_HDR_BY0_4: J9.15 U25.8(2B1) ; also on sheet 5
USB_FD5: U18.55(PB5/FD5) U25.40(2A2)
USB_FD5/TST_HDR_BY0_5: J9.17 U25.9(2B2) ; also on sheet 5
USB_FD6: U18.56(PB6/FD6) U25.38(2A3)
USB_FD6/TST_HDR_BY0_6: J9.19 U25.11(2B3) ; also on sheet 5
USB_FD7: U18.57(PB7/FD7) U25.37(2A4)
USB_FD7/TST_HDR_BY0_7: J9.21 U25.12(2B4) ; also on sheet 5
USB_FD8: U18.102(PD0/FD8) U25.36(3A1)
USB_FD8/TST_HDR_BY1_0: J9.23 U25.13(3B1) ; also on sheet 5
USB_FD9: U18.103(PD1/FD9) U25.35(3A2)
USB_FD9/TST_HDR_BY1_1: J9.25 U25.14(3B2) ; also on sheet 5
USB_FD10: U18.104(PD2/FD10) U25.33(3A3)
USB_FD10/TST_HDR_BY1_2: J9.27 U25.16(3B3) ; also on sheet 5
USB_FD11: U18.105(PD3/FD11) U25.32(3A4)
USB_FD11/TST_HDR_BY1_3: J9.29 U25.17(3B4) ; also on sheet 5
USB_FD12: U18.121(PD4/FD12) U25.30(4A1)
USB_FD12/TST_HDR_BY1_4: J9.31 U25.19(4B1) ; also on sheet 5
USB_FD13: U18.122(PD5/FD13) U25.29(4A2)
USB_FD13/TST_HDR_BY1_5: J9.33 U25.20(4B2) ; also on sheet 5
USB_FD14: U18.123(PD6/FD14) U25.27(4A3)
USB_FD14/TST_HDR_BY1_6: J9.35 U25.22(4B3) ; also on sheet 5
USB_FD15: U18.124(PD7/FD15) U25.26(4A4)
USB_FD15/TST_HDR_BY1_7: J9.37 U25.23(4B4) ; also on sheet 5
USB_FPGA_CLK: U18.50(TXD0) ; also on sheet 8
USB_FPGA_D: U18.111(PE3) ; also on sheet 8
USB_FPGA_DONE_IV: U18.83(PA1/INT1#) ; also on sheet 8
USB_FPGA_INIT_B: U18.84(PA2/SLOE) ; also on sheet 8
USB_FPGA_PROGB: U18.89(PA4/FIFOADR0) ; also on sheet 8
USB_FPGA_RESET: U18.90(PA5/FIFOADR1) U26.29(4A2)
USB_FPGA_RESET/TST_HDR_BY3_5: J9.34 U26.20(4B2) ; also on sheet 5
USB_GPIO_B0: U18.108(PE0) ; also on sheet 4
USB_GPIO_B1: U18.109(PE1) ; also on sheet 4
USB_GPIO_B2: U18.110(PE2) ; also on sheet 4
USB_GPIO_B3: U18.112(PE4) ; also on sheet 4
USB_GPIO_B4: U18.113(PE5) ; also on sheet 4
USB_GPIO_B5: U18.114(PE6) ; also on sheet 4
USB_GPIO_B6: U18.91(PA6/PKTEND) ; also on sheet 4
USB_GPIO_B7: U18.92(PA7/FLAGD/SLCS) ; also on sheet 4
USB_IF_CLK/TEST_CLK_0: J9.5 R34.1 ; also on sheet 5
USB_INT5#: R3.1 U18.106(INT5) U26.27(4A3)
USB_INT5#/TST_HDR_BY3_6: J9.36 U26.22(4B3) ; also on sheet 5
USB_MICTOR_OE#: J5.2 R30.1 U25.1(1~{OE}) U25.24(4~{OE}) U25.25(3~{OE}) U25.48(2~{OE}) U26.1(1~{OE}) U26.24(4~{OE}) U26.25(3~{OE}) U26.48(2~{OE})
USB_RDY0: U18.4(RDY0/SLRD) ; also on sheet 5
USB_RDY1: U18.5(RDY1/SLWR) ; also on sheet 5
USB_RDY2: U18.6(RDY2) ; also on sheet 5
VOFF_2: C148.1 FB7.1 ; also on sheet 14
N12482172: R138.2 U18.32(IFCLK)
N12487904: R10.2 U18.101(WAKEUP)
N12531568: R14.2 U18.99(RESET#)
N12533200: C21.1 R13.2 R14.1
N12538869: R127.1 R129.2 U18.85(PA3/WU2)
N12560917: R26.1 U18.28(INT4)
N12564506: R28.1 U18.29(T0)
N12565709: R32.1 U18.30(T1)
N12566914: R35.1 U18.31(T2)
N12568869: R20.1 U18.7(RDY3)
N12570070: R22.1 U18.8(RDY4)
N12571273: R25.1 U18.9(RDY5)
N12598472: R139.1 U18.35(EA)
N12676352: C163.1 D14.1(VCC) FB8.1 J1.1(5V)
N12739603: C175.1 U18.12(XTALIN) Y5.2
N12742169: C168.1 U18.11(XTALOUT) Y5.1
N12857231: J7.2 R143.2 U19.2(A1)
N14646526: D1.2(CATHODE) R29.1
N18950967: Q5.1(BASE) R33.2 R140.2
N19386929: L8.1 U16.1(L)
N19387896: L8.2 U16.10(SW)
N19409179: R113.1 U16.5(FB)
N19410163: C149.2 R113.2 R115.2 R116.1
N19412140: C145.1 C149.1 R110.1 R115.1 U16.9(VOUT)
N19423987: C144.1 U16.3(SS)
N19433144: C1.1 C7.1 FB1.2 U1.3(VTT) U1.5(VTTSNS)
N19433283: C14.1 U1.6(VTTREF)
N19433301: C11.1 FB1.1 R4.1
N19458944: C37.1 U4.17(VBIAS)
N19472425: C26.2 L1.1 U4.6(PH0) U4.7(PH1) U4.8(PH2) U4.9(PH3) U4.10(PH4)
N19481582: C40.1 L1.2 R41.1 U4.2(VSENSE)
N19496784: C26.1 U4.5(BOOT)
N19536249: C62.1 U7.25(VBIAS)
N19564427: C65.1 U7.5(BOOT)
N19565621: C65.2 L2.1 U7.6(PH0) U7.7(PH1) U7.8(PH2) U7.9(PH3) U7.10(PH4) U7.11(PH5) U7.12(PH6) U7.13(PH7) U7.14(PH8)
N19610507: C85.1 L2.2 R61.1 U7.2(VSENSE)
N19623241: C96.2 L3.1 U12.6(PH0) U12.7(PH1) U12.8(PH2) U12.9(PH3) U12.10(PH4) U12.11(PH5) U12.12(PH6) U12.13(PH7) U12.14(PH8)
N19623245: C103.1 L3.2 R91.1 U12.2(VSENSE)
N19623255: C95.1 U12.25(VBIAS)
N19623373: C96.1 U12.5(BOOT)
N20882996: C152.1 FB7.2 J14.13A(DMDVCC2_0) J14.13B(DMDVCC2)
N20883028: C139.1 FB5.2 J14.25E(DMD3P3VB1) J14.25F(DMD3P3VB0)
N20883056: C133.1 FB4.2 J14.1B(DMD3P3VA0) J14.1C(DMD3P3VA1)
N35815705: R168.2 U23.7(~{PF}0)
N35930174: R160.2 R169.2 U23.6(PFI)
N37614906: R151.1 R152.1 U19.7(WP)
N37706222: TP8.1(TP) U18.34(BKPT)
N38502459: R137.1 U18.1(CLKOUT)
N38505147: R34.2 R137.2 R138.1
N39071155: C151.1 L9.2 R117.1 R120.1 R264.2
N39071167: C141.2 L9.1 U17.6(PH0) U17.7(PH1) U17.8(PH2) U17.9(PH3) U17.10(PH4)
N39071184: C138.2 C286.1 R103.1 R104.2 R106.1 U17.2(VSENSE)
N39071297: C141.1 U17.5(BOOT)
N39071309: R106.2 R262.2 R264.1
N39071470: C143.1 U17.17(VBIAS)
N39071546: C286.2 R262.1
N39711612: C136.2 R104.1
N39714072: C136.1 C138.1 U17.3(COMP)

Not connected (* = marked no-connect by the designer): D14 2(NC)*; J1 4(NC)*; J8 1* 5* 7* 9* 11*; J9 1* 2* 4* 6* 38*; U4 3(NC)* 4(PWRGD)* 20(RT)*; U7 3(NC)* 28(RT)*; U12 3(NC)* 4(PWRGD)* 28(RT)*; U17 19(SYNC)* 20(RT)*; U18 14(NC_1)* 15(NC_2)* 16(NV_3)* 21(A11)* 22(A12)* 23(A13)* 24(A14)* 25(A15)* 38(OE#)* 39(PSEN#)* 40(RD#)* 41(WR#)* 42(CS#)* 51(RXD0)* 52(TXD1)* 53(RXD1)* 59(D0)* 60(D1)* 61(D2)* 62(D3)* 63(D4)* 67(CTL4)* 86(D5)* 87(D6)* 88(D7)* 94(A0)* 95(A1)* 96(A2)* 97(A3)* 98(CTL5)* 117(A4)* 118(A5)* 119(A6)* 120(A7)* 126(A8)* 127(A9)* 128(A10)*; U23 1(~{RESET})* 8(NC)*; U26 23(4B4)* 26(4A4)*

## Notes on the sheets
sheet 16
- FLEX CONNECTOR B
- NOTE: Do Not Install
- DMD FLEX B
- DLP010
sheet 17
- EXP 1
- EXP CONNECTOR 1
- DLP010
sheet 18
- EXP 2
- EXP CONNECTOR 2
- DLP010
sheet 19
- 3.3V 3A
- 12V 0.5A
- 0.9V 1A
- 2.5V 6A
- NOTE: Do Not Install
- 1.8V 6A
- NOTE: Do Not Install
- POWER 1
- DLP010
sheet 20
- 1.0V 3A
- NOTE: Do Not Install
- POWER 2
- DLP010
sheet 21
- 0-1 USB SIGNALS DISCONNECTED
  1-2 USB SIGNALS CONNECTED
  2-3 USB SIGNALS AUTO
- OE#      Function
- L      A=B
  H    Disconect
- TEST HEADERS
- DLP010
sheet 22
- NOTE: Do Not Install
- NOTE: Do Not Install
- To disconnect SDA and SCL lines to Cypress part: replace NP with 2.2K ohms
  reisistors,  remove 0 k ohms resistors.
- NOTE: Do Not Install
- USB CONTROLLER
- DLP010
